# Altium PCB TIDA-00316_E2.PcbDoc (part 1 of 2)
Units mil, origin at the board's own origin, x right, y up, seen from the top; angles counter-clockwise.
Board outline 3345 x 4425 mil, 4 copper layers (Top Layer, L1_GND, L2_POWER, Bottom Layer), stack 90 mil thick; 218 components, 101 nets, 687 pads, 221 vias.
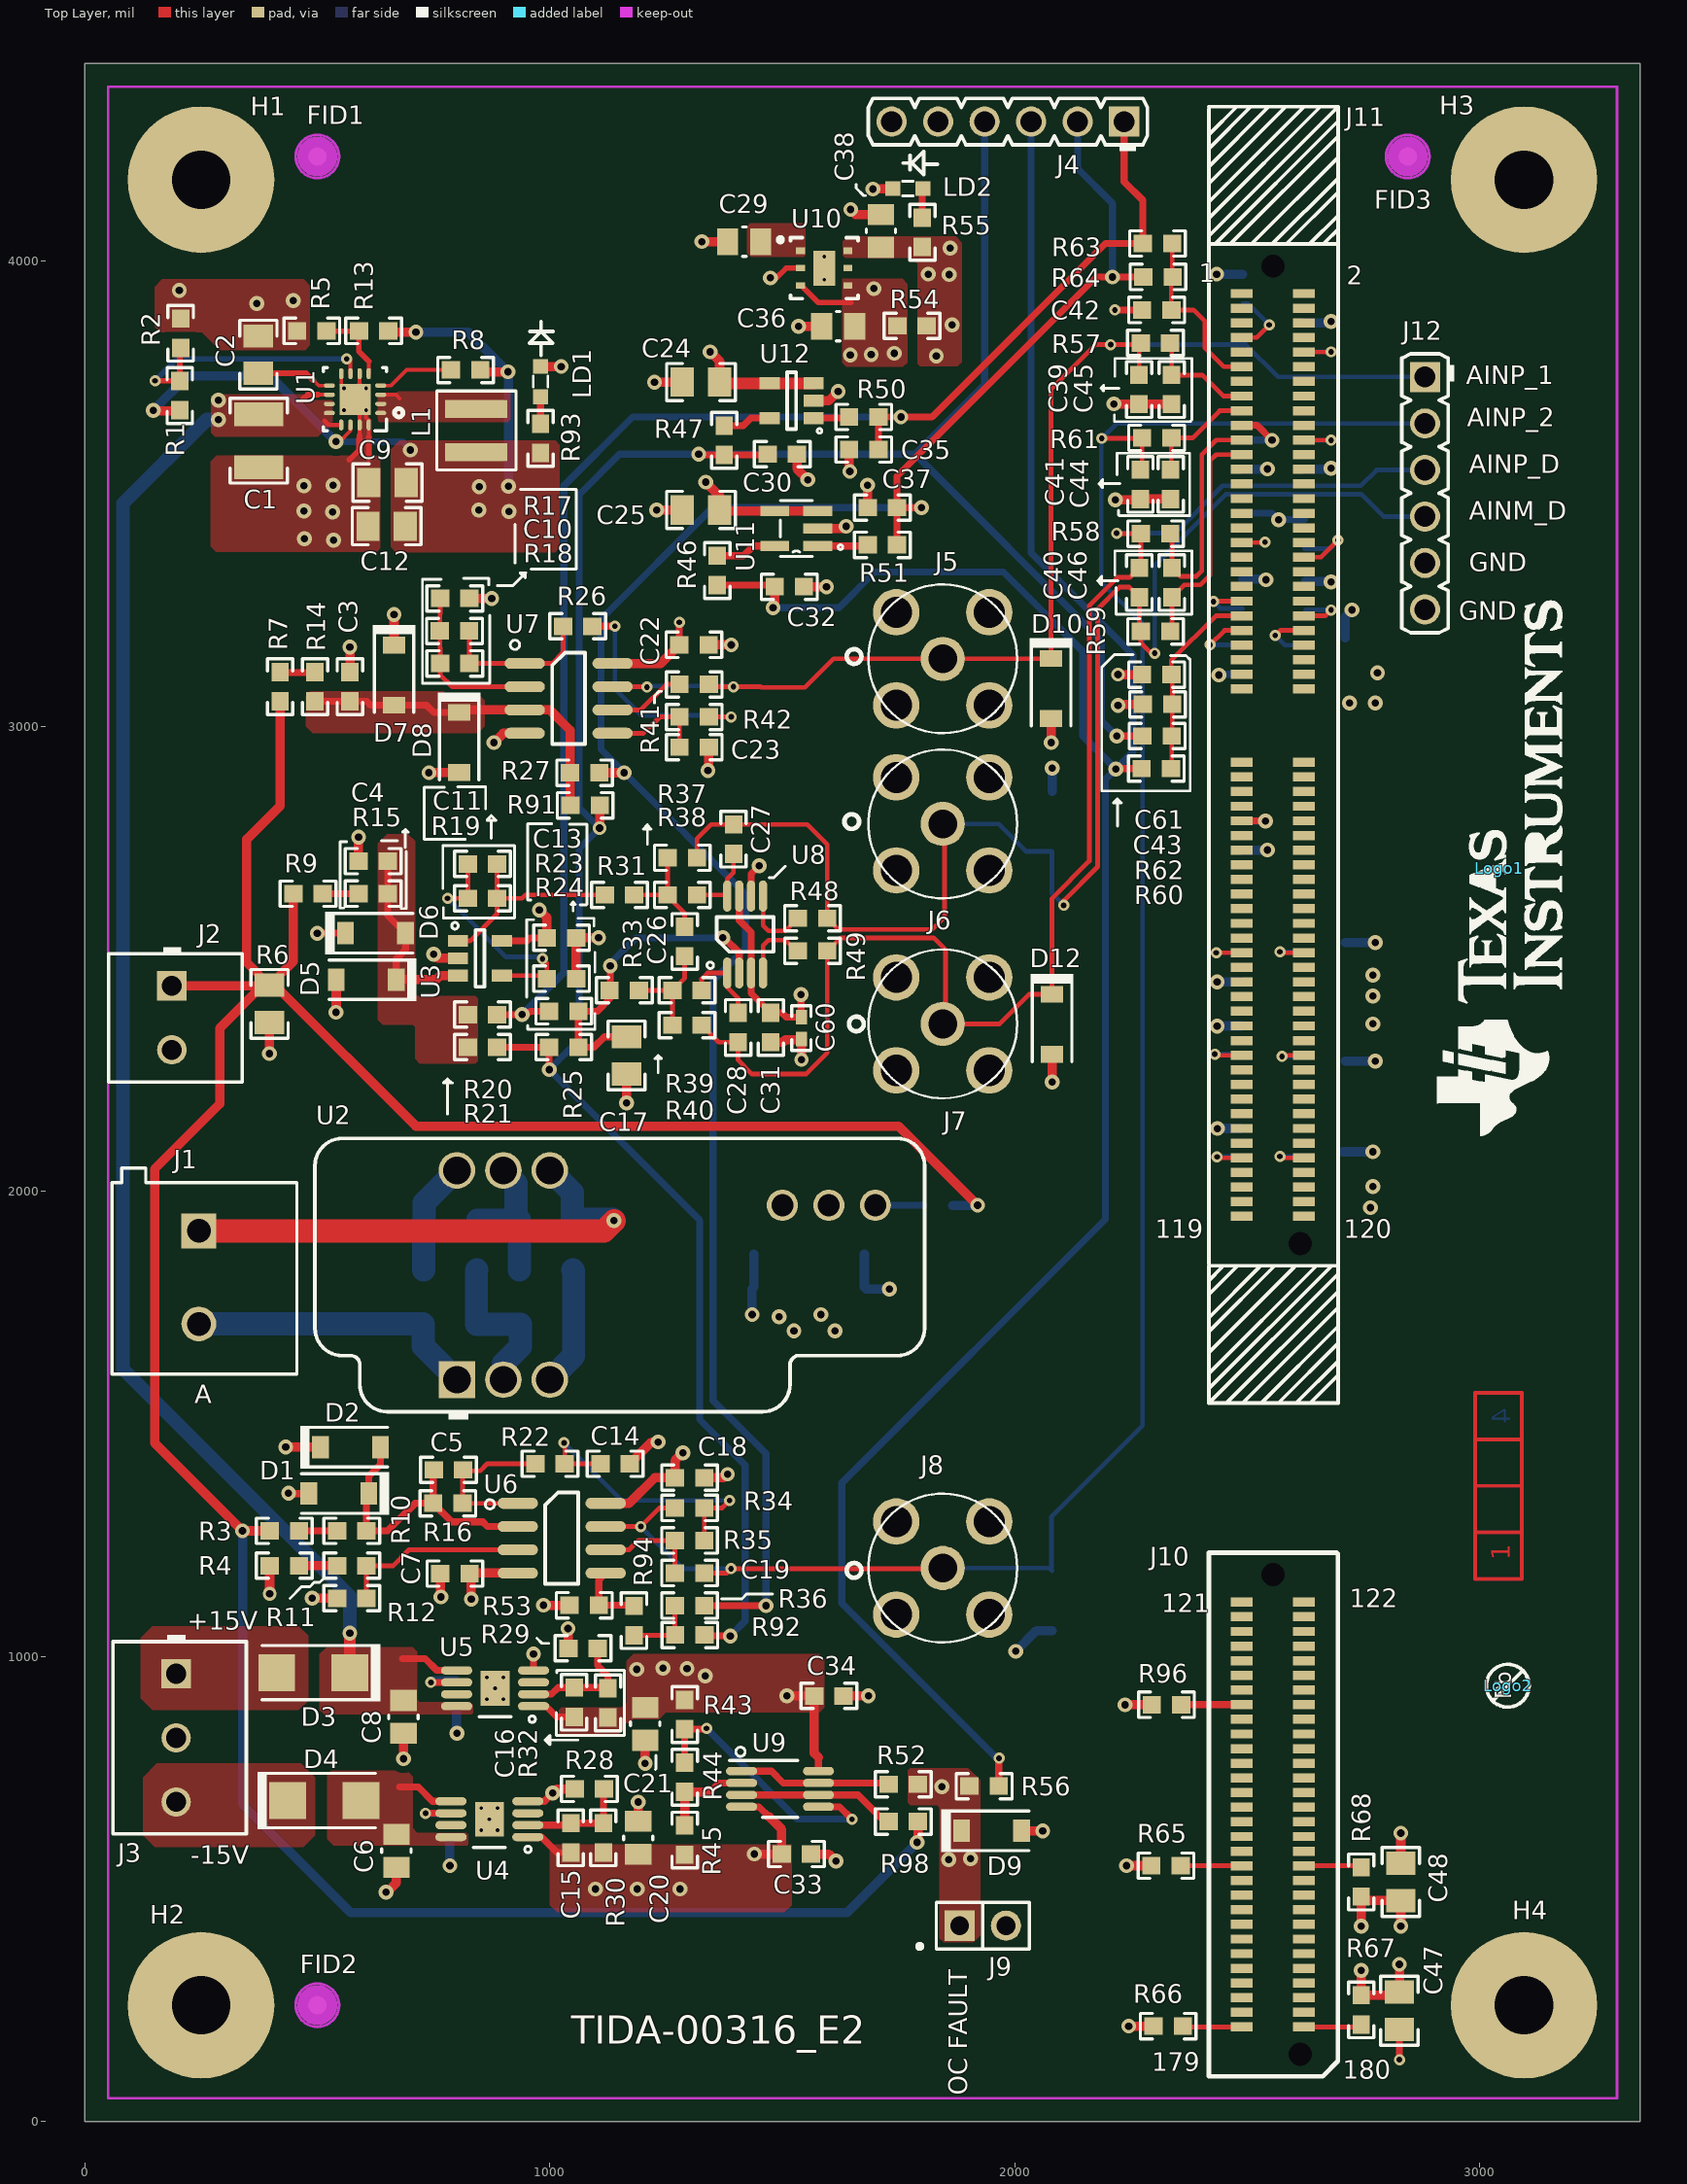
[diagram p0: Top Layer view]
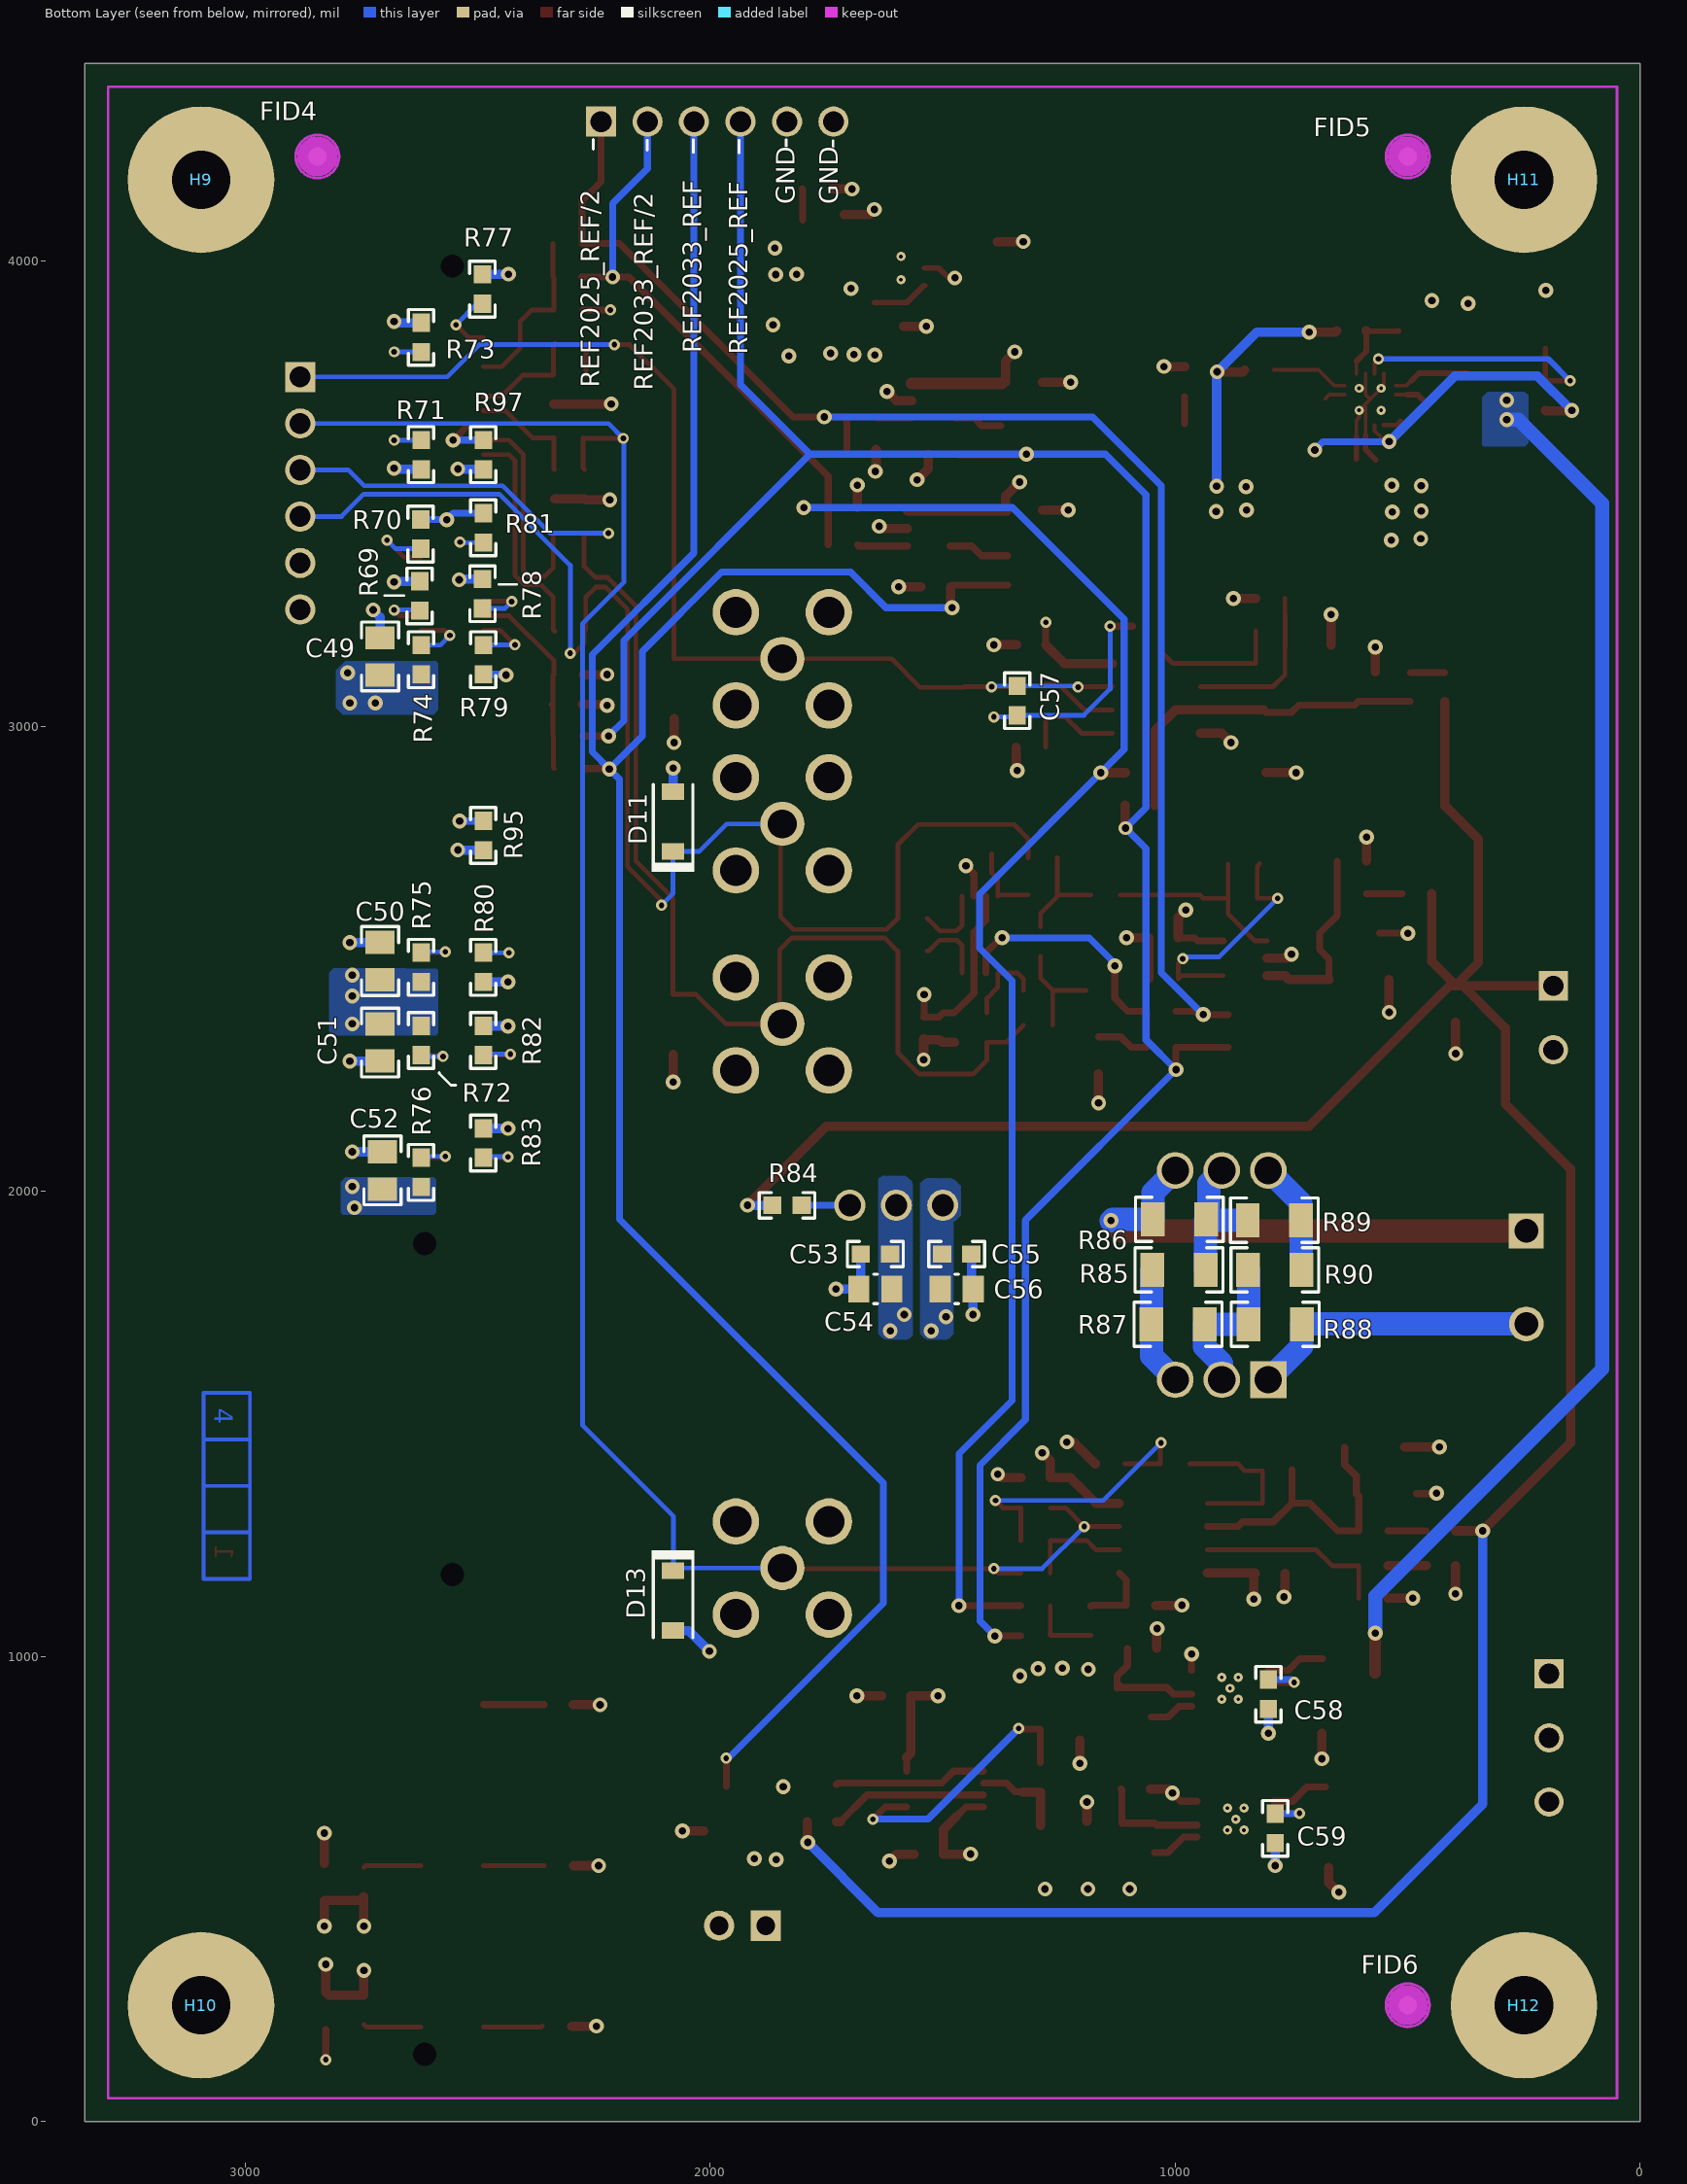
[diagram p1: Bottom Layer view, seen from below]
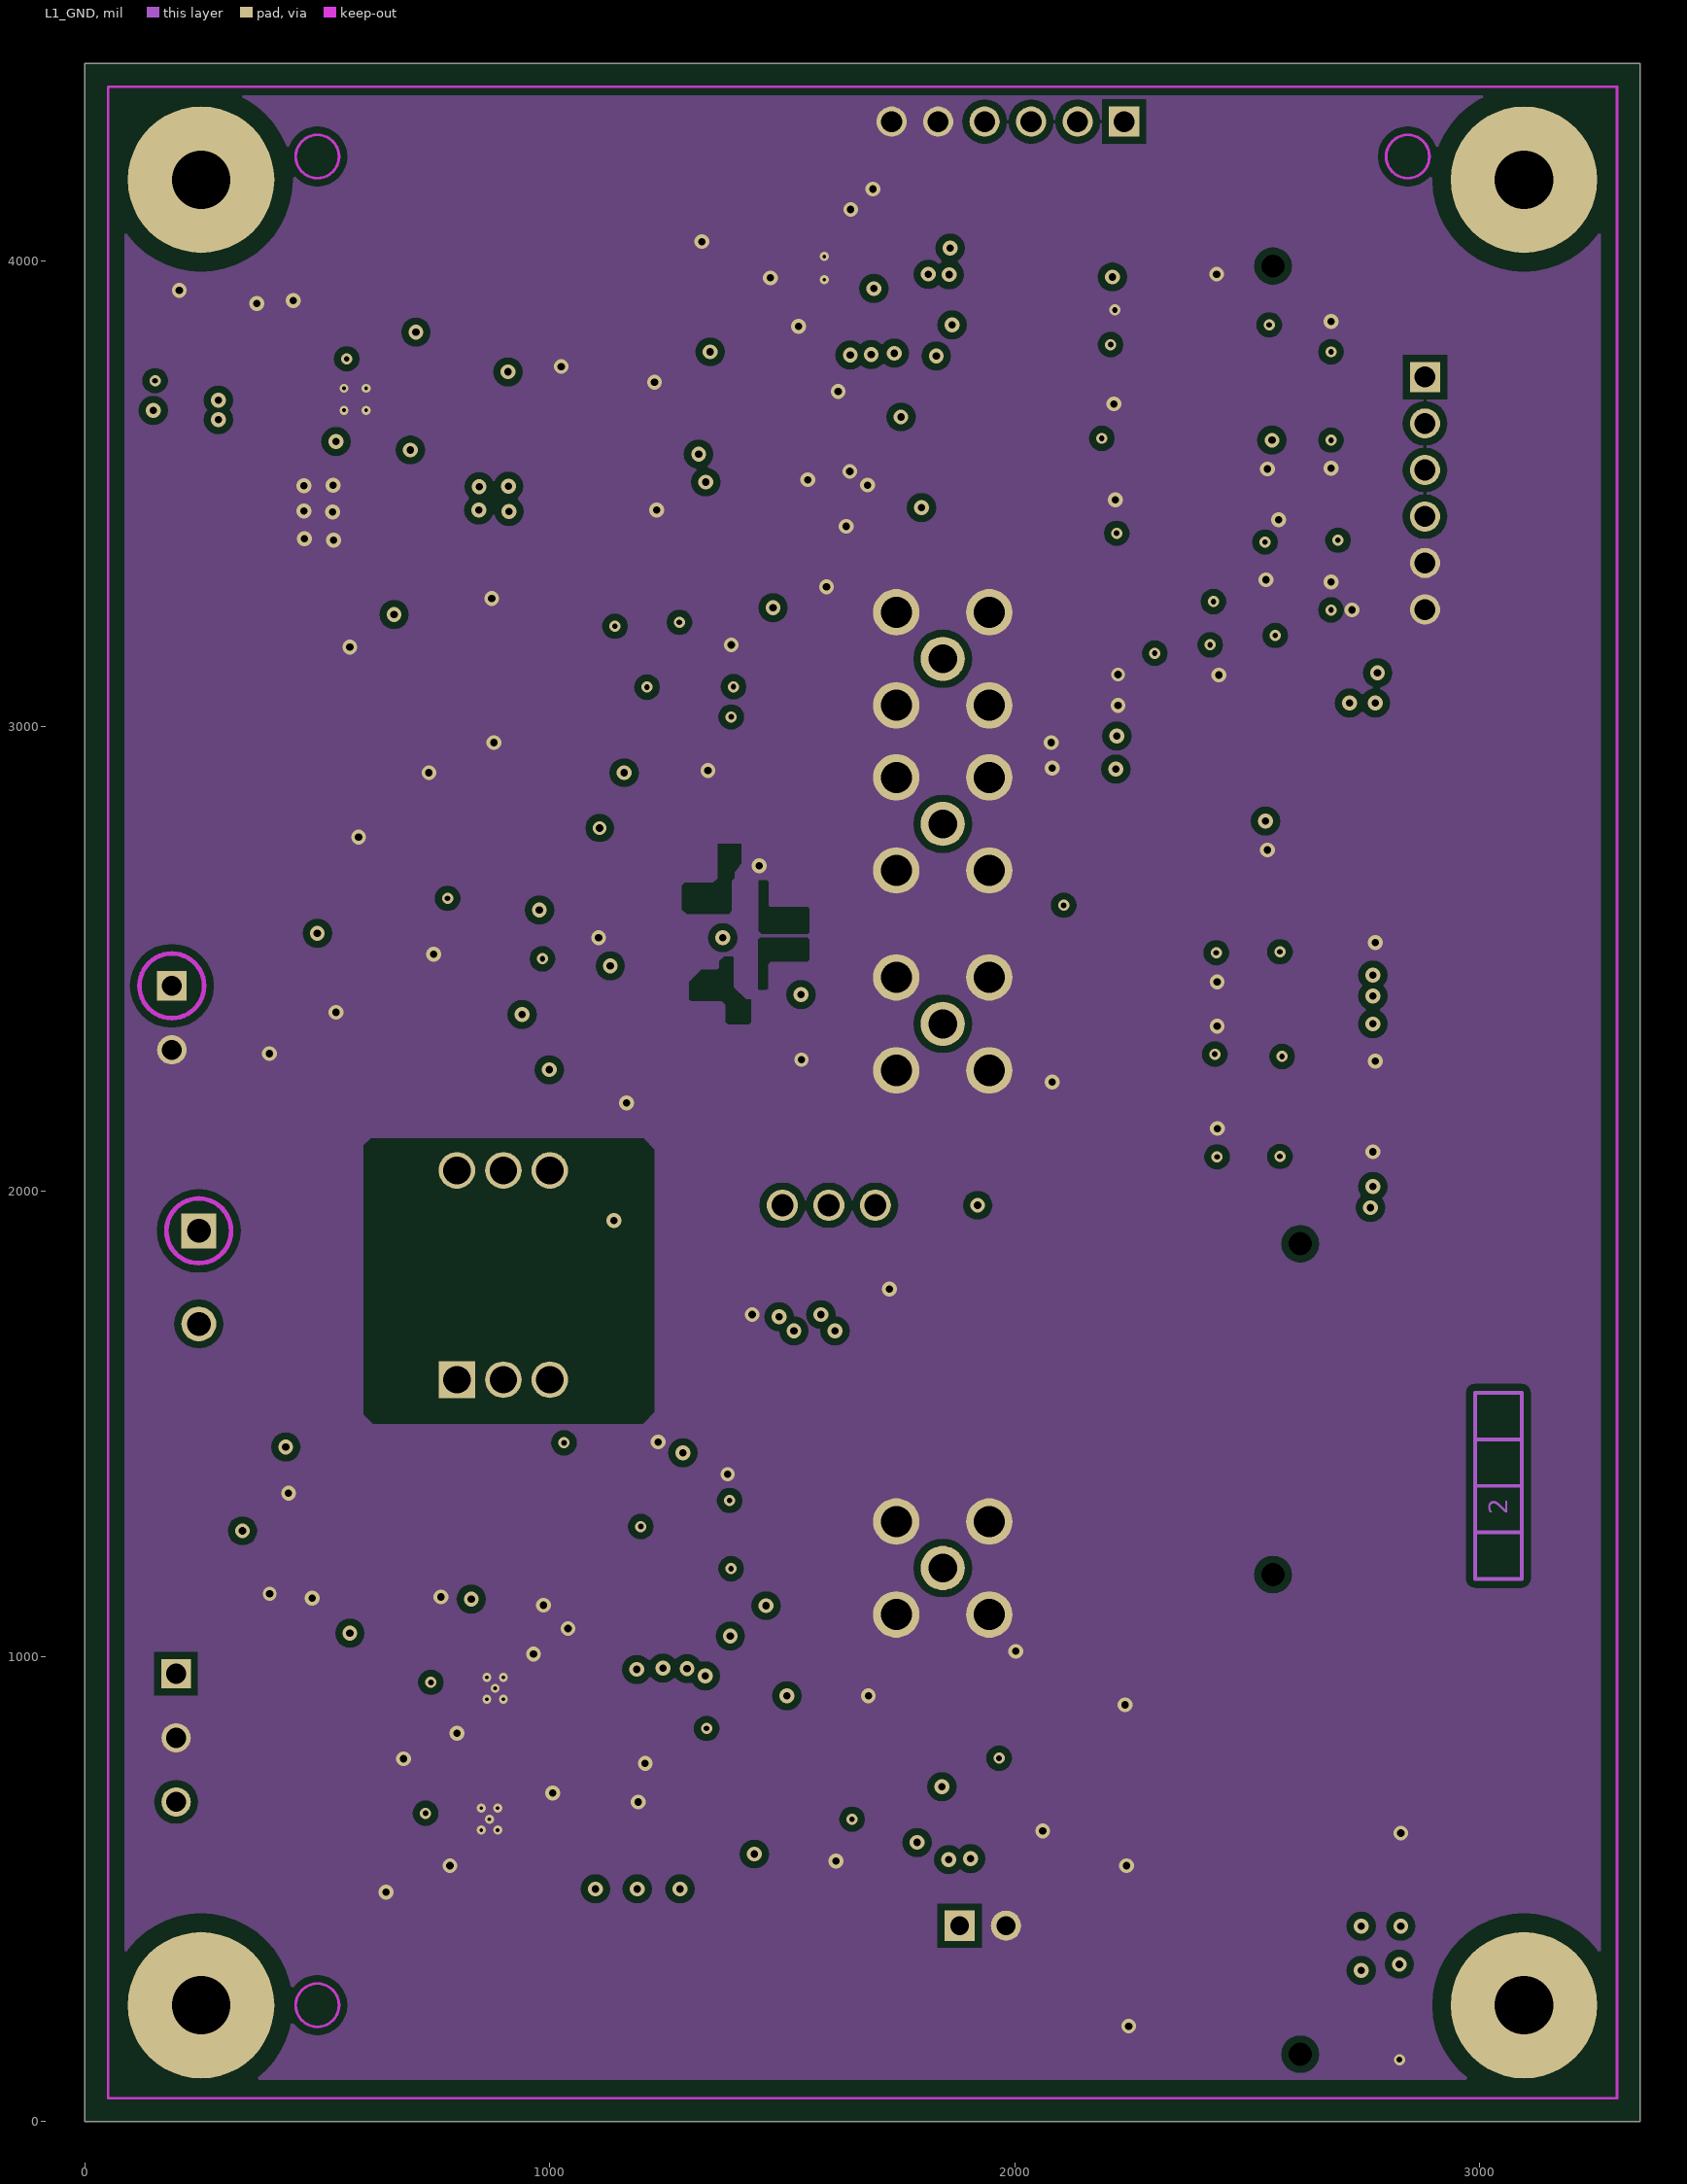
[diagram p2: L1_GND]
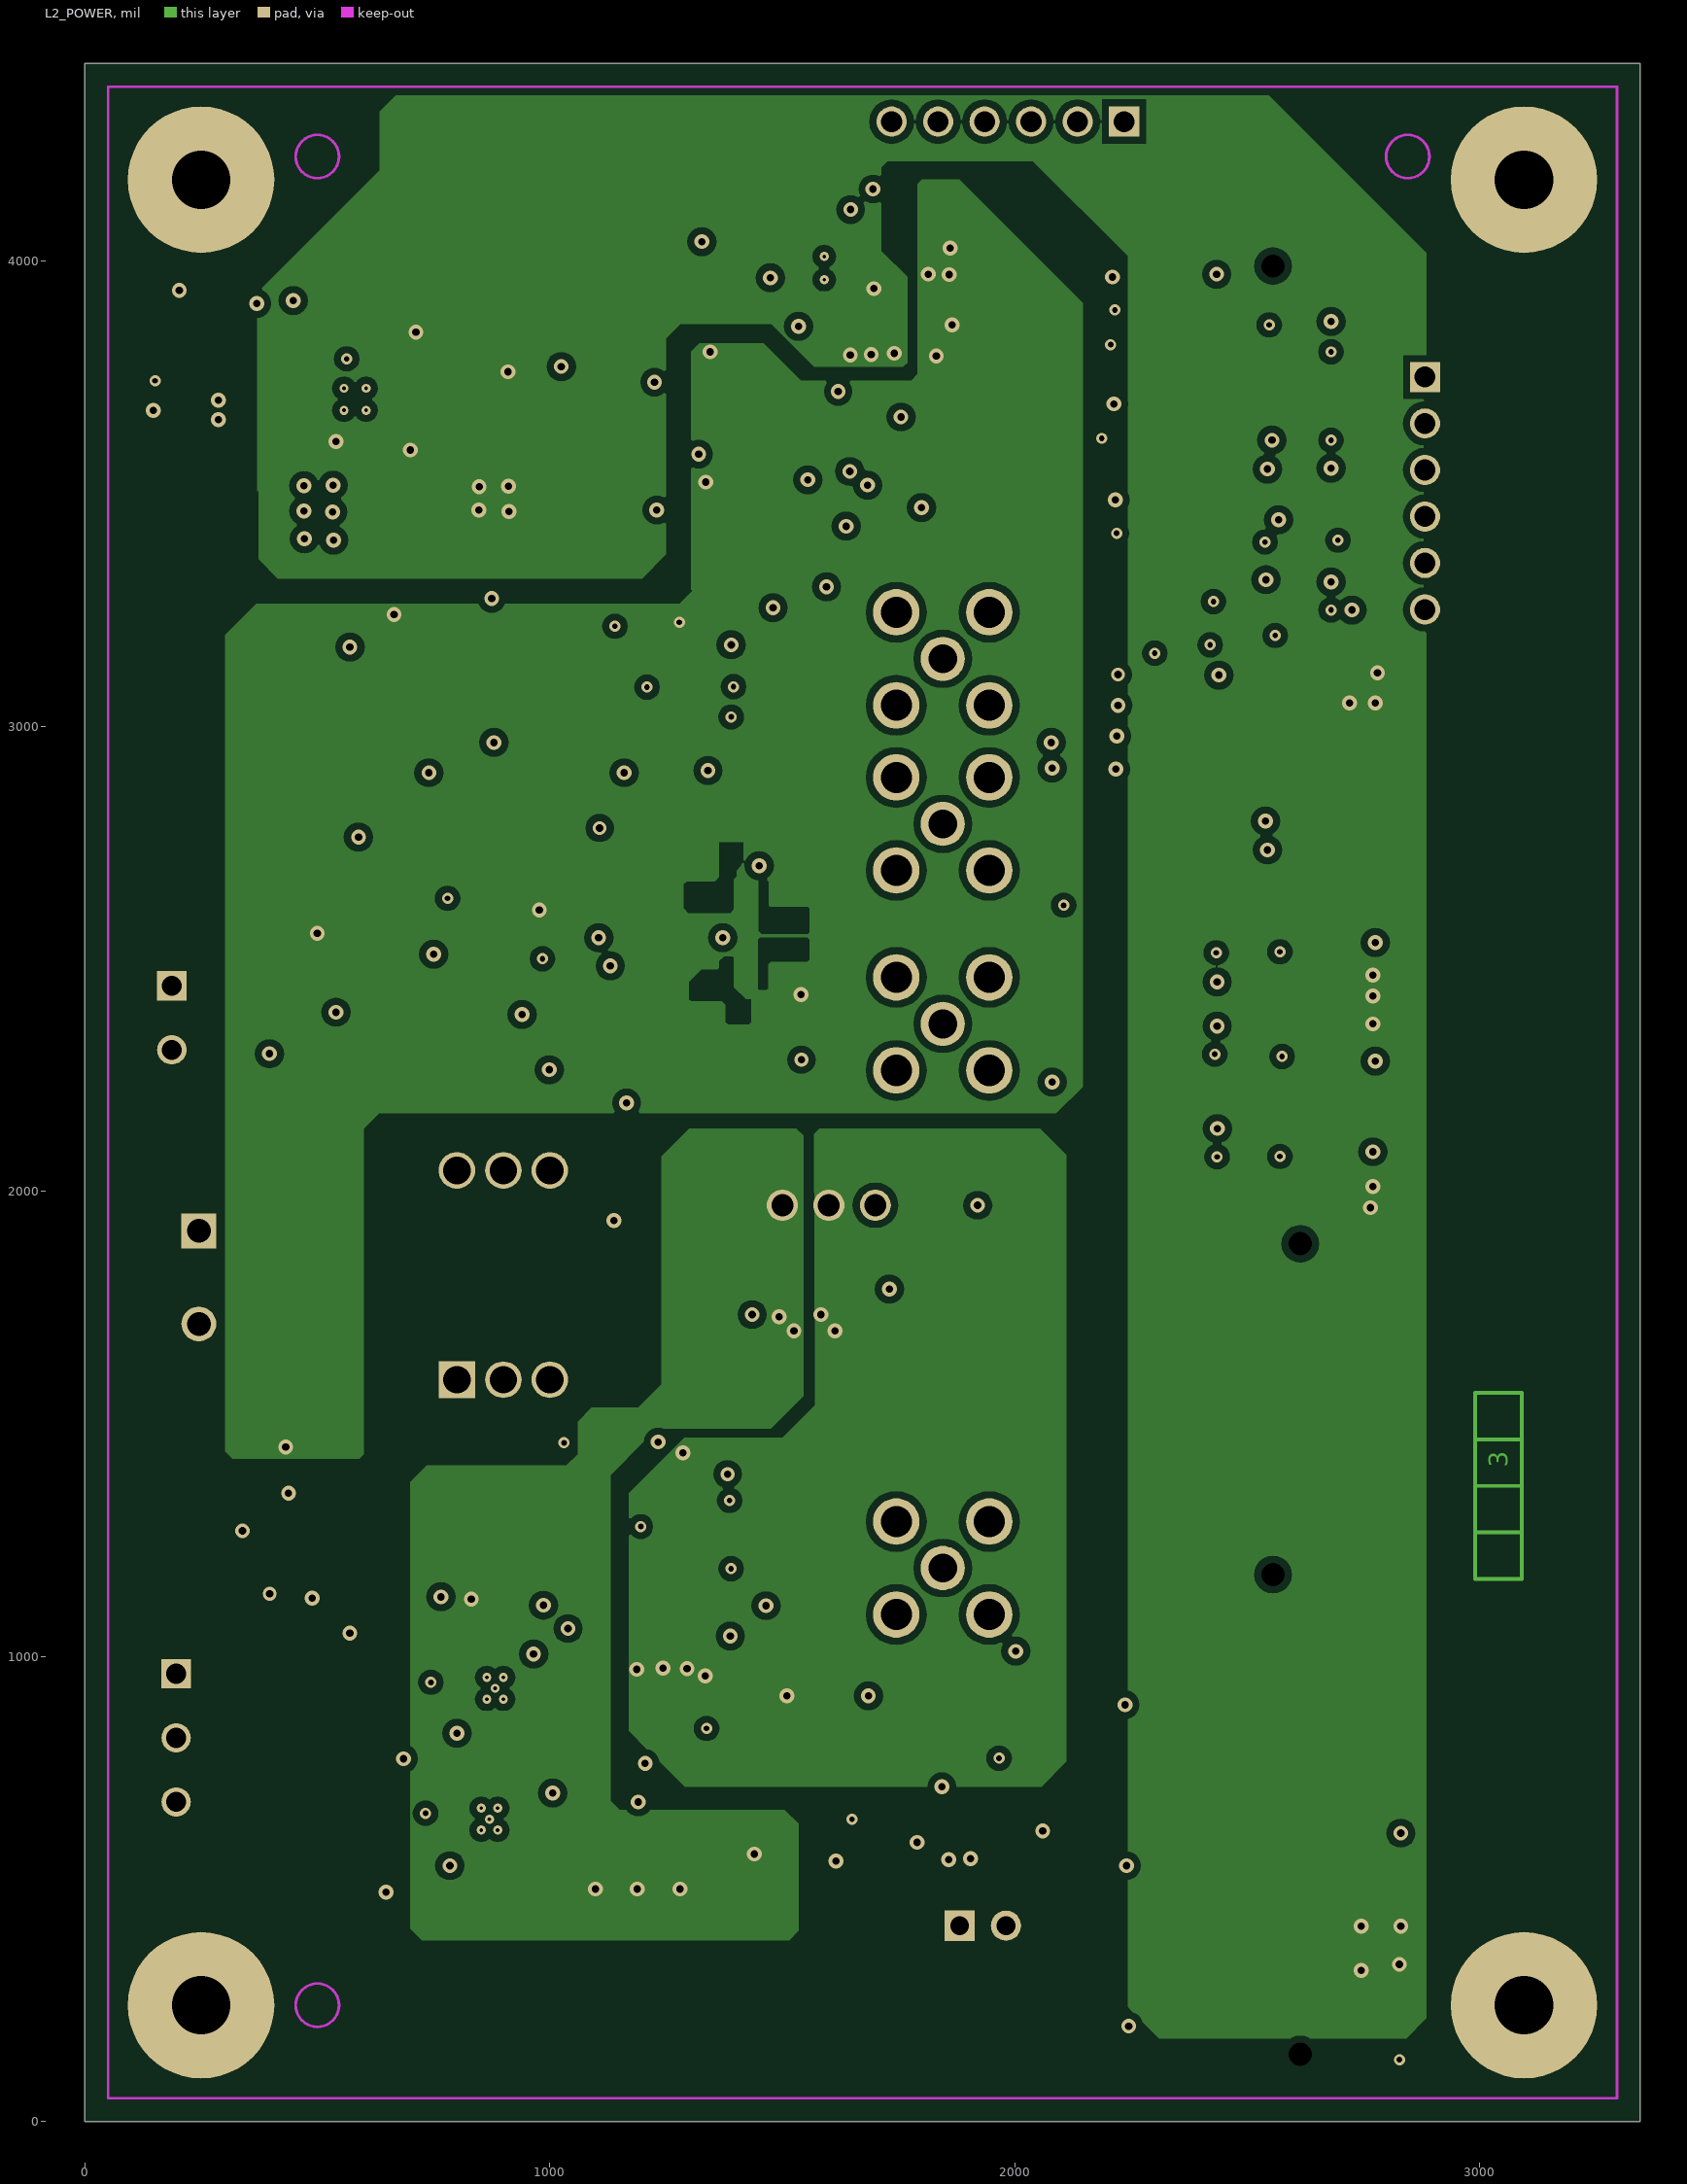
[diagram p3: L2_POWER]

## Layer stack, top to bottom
Top Layer: signal copper 1.4
Dielectric: core 59.2, FR-4, Dk 4.8
L1_GND: signal copper 1.4
Dielectric: prepreg 12.6, FR-4, Dk 4.8
L2_POWER: signal copper 1.4
Dielectric: core 12.6, FR-4, Dk 4.8
Bottom Layer: signal copper 1.4

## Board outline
0,0 3345,0 3345,4425 0,4425

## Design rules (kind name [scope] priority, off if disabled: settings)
AcuteAngle [All] p1: minimum=4.50000000000000E+0001 checktracksonly=FALSE
AssemblyTestPointUsage [All] p1: valid=2
Clearance Clearance_Boardedge_poly [OnCopper and InPolygon vs IsKeepOut] p1: gap=15
Clearance "Clearance_via_thr pin" [IsVia vs IsThruPin] p2: gap=8
Clearance Clearance_MTG_COPPER [InPadClass('MTG') vs InPolygon] p3: gap=40
Clearance "Clearance_pad _class" [InPadClass('U8')] p4: gap=7.8
Clearance "shape to all" [InPolygon] p5: gap=15
Clearance "Shape to Shape" [InPolygon vs InPolygon] p6: gap=25
Clearance "SMD to Via" [IsSMTPin vs IsVia] p7: gap=8
Clearance [All] p8: gap=8
DiffPairsRouting DiffPair_DiffPairsRouting [InDifferentialPair ('kan')] p1: maxlimit=10 minlimit=10 mostfreqgap=10 maxuncoupledlength=500
DiffPairsRouting DiffPair_DiffPairsRouting_1 [InDifferentialPair ('kan')] p2: maxlimit=10 minlimit=10 mostfreqgap=10 maxuncoupledlength=500
DiffPairsRouting [All] p3: maxlimit=100 minlimit=10 mostfreqgap=10 maxuncoupledlength=1000
FabricationTestPointUsage TestPointUsage [All] p1: valid=2 allowmultiple=FALSE
FabricationTestpoint Testpoint [All] p1: side=3 testpointundercomponent=TRUE minsize=40 maxsize=100 preferedsize=60 minholesize=0 maxholesize=40 preferedholesize=32 testpointgrid=1 allowsidetop=TRUE allowsidebottom=TRUE usegrid=TRUE gridtolerance=0.01
FanoutControl Fanout_LCC [IsLCC] p1: bgadir=Out bgaviamode=Centered fanoutstyle=Auto fanoutdirection=Alternating viagrid=1 // Fanout_LCC (Default Rule)
FanoutControl Fanout_BGA [IsBGA] p2: bgadir=Out bgaviamode=Centered fanoutstyle=Auto fanoutdirection=Alternating viagrid=1 // Fanout_BGA (Default Rule)
FanoutControl Fanout_Default [All] p4: bgadir=Out bgaviamode=Centered fanoutstyle=Auto fanoutdirection=Alternating viagrid=1 // Fanout_Default (Default Rule)
FanoutControl Fanout_Small [(CompPinCount < 5)] p5: bgadir=Out bgaviamode=Centered fanoutstyle=Auto fanoutdirection=OutThenIn viagrid=1 // Fanout_Small (Default Rule)
HoleSize [All] p1: absolutevalues=TRUE maxlimit=251 minlimit=7 maxpercent=80.000 minpercent=20.000
MatchedLengths DiffPair_MatchedLengths [InDifferentialPair ('kan')] p1: tolerance=1000 checknetsindiffpair=TRUE checkdiffpairvsdiffpair=TRUE checkothers=TRUE
MatchedLengths DiffPair_MatchedLengths_1 [InDifferentialPair ('kan')] p2: tolerance=1000 checknetsindiffpair=TRUE checkdiffpairvsdiffpair=TRUE checkothers=TRUE
MinimumAnnularRing [All] p1: minimumring=5
MinimumAnnularRing MinimumAnnularRing_ThermalPadVias [IsVia and InAnyComponent] p2: minimumring=5.91
MinimumSolderMaskSliver MinimumSolderMaskSliver_Logo [InComponentClass('Logo') vs InComponentClass('Logo')] p1: minsoldermaskwidth=0.7
MinimumSolderMaskSliver [All] p2: minsoldermaskwidth=3.94
PlaneClearance [All] p1: clearance=15
PlaneConnect [All] p1: planeconnectstyle=Direct reliefexpansion=10 reliefentries=4 reliefconductorwidth=10 reliefairgap=10
PolygonConnect [All] p1: connectstyle=Direct reliefconductorwidth=10 reliefentries=4 polygonreliefangle="90 Angle" airgapwidth=10
RoutingVias RoutingVias_power [InNetClass('POWER')] p1: holewidth=16 width=32 viastyle="Through Hole" minholewidth=7.87 minwidth=19.68 maxholewidth=16 maxwidth=32
RoutingVias ThermalPadVias [IsVia and InAnyComponent] p2: holewidth=8 width=20 viastyle="Through Hole" minholewidth=7.87 minwidth=19 maxholewidth=12 maxwidth=24
RoutingVias [All] p3: holewidth=12 width=24 viastyle="Through Hole" minholewidth=12 minwidth=24 maxholewidth=16 maxwidth=32
SMDToCorner [All] p1: distance=30000
SilkToSilkClearance [All] p1: silktosilkclearance=5
SilkscreenOverComponentPads [IsPad] p1: minsilkscreentomaskgap=5
SolderMaskExpansion [All] p1: expansion=3
Width Width_power [InNetClass('POWER')] p1: maxlimit=100 minlimit=8 preferedwidth=20
Width [All] p2: maxlimit=100 minlimit=8 preferedwidth=10 checkconnectedcopper=TRUE
14 further rules are at their usual default settings.

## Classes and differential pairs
pad class MTG: H1-1 H2-1 H3-1 H4-1
component class SH05_180_pin_connector_interface: C39 C40 C41 C42 C43 C44 C45 C46 C47 C48 C49 C50 C51 C52 C61 D10 D11 D12 D13 J10 J11 R57 R58 R59 R60 R61 R62 R63 R64 R65 R66 R67 R68 R69 R70 R71 R72 R73 R74 R75 R76 R77 R78 R79 R80 R81 R82 R83 R95 R96 R97
component class SH04_Fully_differential_ended_SC_to_ADC: C4 C11 C13 C17 C26 C27 C28 C31 C33 C34 C60 D5 D6 D9 J4 J6 J7 J9 J12 R9 R15 R19 R20 R21 R23 R24 R25 R31 R33 R37 R38 R39 R40 R43 R44 R45 R48 R49 R52 R56 R98 U3 U8 U9
component class SH03_Single_ended_SC_to_ADC: C3 C5 C7 C10 C14 C18 C19 C22 C23 C53 C54 C55 C56 C57 D1 D2 D7 D8 J1 J2 J5 J8 R3 R4 R6 R7 R10 R11 R12 R14 R16 R17 R18 R22 R26 R27 R34 R35 R36 R41 R42 R53 R84 R85 R86 R87 R88 R89 R90 R91 R92 R94 U2 U6 U7
component class SH02_Power_supply: C1 C2 C6 C8 C9 C12 C15 C16 C20 C21 C24 C25 C29 C30 C32 C35 C36 C37 C38 C58 C59 D3 D4 J3 L1 LD1 LD2 R1 R2 R5 R8 R13 R28 R29 R30 R32 R46 R47 R50 R51 R54 R55 R93 U1 U4 U5 U10 U11 U12
component class "Mounting Holes": H1 H2 H3 H4
component class Header: J4 J9 J12
component class AssemblyNote: ZZ1 ZZ2 ZZ3
component class Logo: Logo1
component class SH06_Hardware: FID1 FID2 FID3 FID4 FID5 FID6 H1 H2 H3 H4 H9 H10 H11 H12 Logo1 Logo2 ZZ1 ZZ2 ZZ3
component class FiducialMark: FID1 FID2 FID3 FID4 FID5 FID6
pad class U8: U4-1 U4-2 U4-3 U4-4 U4-5 U4-6 U4-7 U4-8 U4-9 U5-1 U5-2 U5-3 U5-4 U5-5 U5-6 U5-7 U5-8 U5-9 U8-1 U8-2 U8-3 U8-4 U8-5 U8-6 U8-7 U8-8 U9-1 U9-2 U9-3 U9-4 U9-5 U9-6 U9-7 U9-8

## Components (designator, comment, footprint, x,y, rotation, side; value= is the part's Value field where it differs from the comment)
C1 "C3216X7R1V106M160AC" 1210 374,3614 r270 top (schematic designator C6)
C2 "C0805C332K5RACTU" 0805_HV 373,3799 r90 top (schematic designator C7)
C3 "C1608C0G2A101J" 0603 570,3085 r90 top (schematic designator C31)
C4 "C1608C0G2A101J" 0603 620,2710 r180 top (schematic designator C48)
C5 "C1608C0G2A101J" 0603 782,1401 r180 top (schematic designator C32)
C6 "GRM21BR61E106KA73L" 0805_140 670,582 r270 top (schematic designator C16)
C7 "GRM188R71H104KA93D" 0603 796,1178 r180 top (schematic designator C36)
C8 "GRM21BR61E106KA73L" 0805_140 685,870 r270 top (schematic designator C12)
C9 "C2012X5R1C226K125AC" 0805_HV 651,3524 r180 top (schematic designator C53)
C10 "C1608C0G2A101J" 0603 795,3205 r180 top (schematic designator C24)
C11 "C1608C0G2A101J" 0603 855,2704 r180 top (schematic designator C44)
C12 "C2012X5R1C226K125AC" 0805_HV 649,3430 r180 top (schematic designator C57)
C13 "GRM188R71H104KA93D" 0603 1025,2545 r0 top (schematic designator C46)
C14 "C1608C0G1H272J" 0603 1140.57,1414.22 r0 top (schematic designator C35)
C15 "C1608C0G1E103J" 0603 1045,610 r90 top (schematic designator C17)
C16 "C1608C0G1E103J" 0603 1052.28,901.38 r90 top (schematic designator C13)
C17 "C0805C105K8RACTU" 0805_HV 1164.98,2292.2 r270 top (schematic designator C50)
C18 "GRM188R71H104KA93D" 0603 1300.57,1384.22 r0 top (schematic designator C34)
C19 "06035A471JAT2A" 0603 1300.57,1179.22 r180 top (schematic designator C33)
C20 "GRM21BR61E106KA73L" 0805_140 1190,610 r90 top (schematic designator C18)
C21 "GRM21BR61E106KA73L" 0805_140 1205,855 r270 top (schematic designator C14)
C22 "GRM188R71H104KA93D" 0603 1310,3175 r0 top (schematic designator C29)
C23 "C1608C0G2A101J" 0603 1310.43,2955 r0 top (schematic designator C30)
C24 "C0805C105K8RACTU" 0805_HV 1325,3740 r180 top (schematic designator C9)
C25 "C0805C105K8RACTU" 0805_HV 1325,3465 r180 top (schematic designator C19)
C26 "GRM1885C2A201JA01D" 0603 1289.98,2537.2 r270 top (schematic designator C47)
C27 "C1608C0G1H821J" 0603 1394.98,2757.2 r270 top (schematic designator C43)
C28 "C1608C0G1H821J" 0603 1404.98,2352.2 r90 top (schematic designator C49)
C29 "GRM21BR61E106KA73L" 0805_140 1418,4042 r180 top (schematic designator C3)
C30 "GRM188R71H104KA93D" 0603 1500,3585 r0 top (schematic designator C10)
C31 "GRM188R71H104KA93D" 0603 1474.98,2352.2 r270 top (schematic designator C45)
C32 "GRM188R71H104KA93D" 0603 1515,3300 r0 top (schematic designator C21)
C33 "GRM188R71H104KA93D" 0603 1530,575 r0 top (schematic designator C37)
C34 "GRM188R71H104KA93D" 0603 1600,915 r0 top (schematic designator C39)
C35 "GRM188R71H104KA93D" 0603 1675,3595 r180 top (schematic designator C11)
C36 "GRM21BR61E106KA73L" 0805_140 1620,3860 r180 top (schematic designator C1)
C37 "GRM188R71H104KA93D" 0603 1715,3470 r180 top (schematic designator C22)
C38 "GRM21BR61E106KA73L" 0805_140 1712,4065 r90 top (schematic designator C2)
C39 "C1608C0G1H331F080AA" 0603 2267.2,3724 r270 top (schematic designator C38)
C40 "C1608C0G1H331F080AA" 0603 2267.73,3309 r270 top (schematic designator C51)
C41 "C1608C0G1H331F080AA" 0603 2270,3520 r270 top
C42 "0603ZD475KAT2A" 0603 2305,3895 r180 top (schematic designator C58)
C43 "0603ZD475KAT2A" 0603 2307,3047 r180 top (schematic designator C59)
C44 "C1608C0G1H331F080AA" 0603 2335,3520 r270 top (schematic designator C42)
C45 "C1608C0G1H331F080AA" 0603 2337.2,3724 r270 top (schematic designator C40)
C46 "C1608C0G1H331F080AA" 0603 2337.73,3309 r270 top (schematic designator C52)
C47 "C0805C105K8RACTU" 0805_HV 2827,238 r270 top (schematic designator C5)
C48 "C0805C105K8RACTU" 0805_HV 2830,515 r90 top (schematic designator C56)
C49 "C0805C105K8RACTU" 0805_HV 2710,3150 r90 bottom (schematic designator C55)
C50 "C0805C105K8RACTU" 0805_HV 2710,2495 r90 bottom (schematic designator C4)
C51 "C0805C105K8RACTU" 0805_HV 2710,2320 r270 bottom (schematic designator C8)
C52 "C0805C105K8RACTU" 0805_HV 2705,2045 r90 bottom (schematic designator C54)
C53 "GRM188R71H104KA93D" 0603 1645,1865 r0 bottom (schematic designator C25)
C54 "GRM21BR61E106KA73L" 0805_140 1645,1790 r0 bottom (schematic designator C26)
C55 "GRM188R71H104KA93D" 0603 1470,1865 r180 bottom (schematic designator C28)
C56 "GRM21BR61E106KA73L" 0805_140 1470,1790 r180 bottom (schematic designator C27)
C57 "GRM1885C2A201JA01D" 0603 1340,3055 r270 bottom (schematic designator C23)
C58 "C1608C0G1E103J" 0603 799.61,918.58 r270 bottom (schematic designator C15)
C59 "C1608C0G1E103J" 0603 785,630 r270 bottom (schematic designator C20)
C60 "C0402C103J5RACTU" 0402 1541,2351 r270 top
C61 "C1608C0G1H331F080AA" 0603 2305,3111 r180 top
D1 "SD101CW-7-F" SOD-123#1 546,1350 r180 top (schematic designator D7)
D2 "SD101CW-7-F" SOD-123#1 571,1450 r0 top (schematic designator D8)
D3 "MBRA160T3G" SMA 491.18,965 r180 top (schematic designator D2)
D4 "MBRA160T3G" SMA 515,690 r0 top (schematic designator D3)
D5 "SD101CW-7-F" SOD-123#1 605,2455 r180 top (schematic designator D11)
D6 "SD101CW-7-F" SOD-123#2 625,2555 r0 top (schematic designator D12)
D7 "SD101CW-7-F" SOD-123#1 665,3110 r270 top (schematic designator D6)
D8 "SD101CW-7-F" SOD-123#1 805,2965 r270 top (schematic designator D5)
D9 "SD101CW-7-F" SOD-123#2 1950,625 r0 top
D10 "MMSZ5227B-7-F" SOD-123#1 2078,3081 r270 top (schematic designator D13)
D11 "MMSZ5227B-7-F" SOD-123#1 2080,2795 r90 bottom (schematic designator D16)
D12 "MMSZ5227B-7-F" SOD-123#1 2080,2359 r270 top (schematic designator D15)
D13 "MMSZ5227B-7-F" SOD-123#1 2080,1120 r270 bottom (schematic designator D14)
FID1 "Fiducial" Fiducial10-20 500,4225 r90 top (schematic designator FID2)
FID2 "Fiducial" Fiducial10-20 500,250 r90 top (schematic designator FID1)
FID3 "Fiducial" Fiducial10-20 2845,4225 r90 top
FID4 "Fiducial" Fiducial10-20 2845,4225 r90 bottom (schematic designator FID6)
FID5 "Fiducial" Fiducial10-20 500,4225 r90 bottom
FID6 "Fiducial" Fiducial10-20 500,250 r90 bottom (schematic designator FID4)
H1 "NY PMS 440 0025 PH" "NY PMS 440 0025 PH" 250,4175 r0 top (schematic designator H2)
H2 "NY PMS 440 0025 PH" "NY PMS 440 0025 PH" 250,250 r0 top (schematic designator H1)
H3 "NY PMS 440 0025 PH" "NY PMS 440 0025 PH" 3095,4175 r0 top
H4 "NY PMS 440 0025 PH" "NY PMS 440 0025 PH" 3095,250 r0 top
H9 "1902C" Keystone_1902C 3095,4175 r180 bottom (schematic designator H7)
H10 "1902C" Keystone_1902C 3095,250 r180 bottom (schematic designator H8)
H11 "1902C" Keystone_1902C 250,4175 r180 bottom (schematic designator H6)
H12 "1902C" Keystone_1902C 250,250 r180 bottom (schematic designator H5)
J1 "1715721" PhoenixContact_1715721 245,1815 r270 top (schematic designator J2)
J2 "39357-0002" Molex_39357-0002 187,2373 r270 top (schematic designator J5)
J3 "39357-0003" Molex_39357-0003 196.18,825 r270 top (schematic designator J1)
J4 "61300611121" WURTH_61300611121 1985,4300 r180 top (schematic designator J9)
J5 "142-0701-201" JOHNSON_142-0701-20X 1845,3145 r0 top (schematic designator J4)
J6 "142-0701-201" JOHNSON_142-0701-20X 1845,2790 r0 top (schematic designator J7)
J7 "142-0701-201" JOHNSON_142-0701-20X 1845,2360 r0 top (schematic designator J8)
J8 "142-0701-201" JOHNSON_142-0701-20X 1845,1190 r0 top (schematic designator J6)
J9 "90120-0122" CONN_90120-0122 1931,421 r0 top (schematic designator J10)
J10 "SPD08-060-RB-TR" HSEC8-130-01-L-DV-A 2555,660 r90 top locked (schematic designator J12)
J11 "SPD08-120-L-RB" HSEC8-160-01-L-DV-A-L 2555,2938.29 r90 top locked
J12 "61300611121" WURTH_61300611121 2882,3501 r270 top (schematic designator J3)
L1 "XFL4020-222MEB" XFL4020 842,3636 r270 top
LD1 "LED_LG L29K-G2J1-24-Z" LED0603AA 980,3741 r270 top (schematic designator LD2)
LD2 "LED_LG L29K-G2J1-24-Z" LED0603AA 1770,4156 r0 top (schematic designator LD1)
Logo1 "Texas Instruments" TI_STACKED_OVERLAY_MEDIUM 3042,2695 r90 top
Logo2 "Pb-Free Symbol" Pb-Free_Overlay_Small 3060,937 r90 top
R1 "CRCW06030000Z0EA" 0603 204,3711 r270 top (schematic designator R52)
R2 "CRCW06030000Z0EA" 0603 206,3845 r270 top
R3 "CRCW06030000Z0EA" 0603 429,1270 r180 top (schematic designator R28)
R4 "CRCW06030000Z0EA" 0603 429,1195 r180 top (schematic designator R34)
R5 "CRCW0603154KFKEA" 0603 488,3850 r0 top (schematic designator R51)
R6 "CRCW080542R2FKEA" 0805_HV 397,2403 r90 top (schematic designator R23)
R7 "CRCW06030000Z0EA" 0603 420,3085 r270 top (schematic designator R21)
R8 "CRCW06031K00FKEA" 0603 819,3766 r0 top (schematic designator R48)
R9 "CRCW06030000Z0EA" 0603 480,2640 r180 top (schematic designator R65)
R10 "RC0603FR-072KL" 0603 574,1270 r0 top (schematic designator R29)
R11 "RC0603FR-072KL" 0603 574,1195 r180 top (schematic designator R35)
R12 "RC0603FR-072KL" 0603 574,1125 r180 top (schematic designator R36)
R13 "CRCW06031M00JNEA" 0603 621,3850 r0 top (schematic designator R50)
R14 "RC0603FR-072KL" 0603 495,3085 r270 top (schematic designator R22)
R15 "RC0603FR-072KL" 0603 620,2640 r0 top (schematic designator R66)
R16 "RC0603FR-072KL" 0603 780.57,1329.22 r180 top (schematic designator R26)
R17 "RC0603FR-072KL" 0603 795.43,3275 r180 top (schematic designator R15)
R18 "RC0603FR-072KL" 0603 795.43,3135 r180 top (schematic designator R12)
R19 "RC0603FR-072KL" 0603 855,2630 r180 top (schematic designator R59)
R20 "RC0603FR-072KL" 0603 855,2380 r180 top (schematic designator R71)
R21 "RC0603FR-072KL" 0603 855,2310 r180 top (schematic designator R17)
R22 "RT0603BRD07673RL" 0603 1000.57,1414.22 r0 top (schematic designator R32)
R23 "RC0603FR-072KL" 0603 1024.98,2457.2 r180 top (schematic designator R62)
R24 "CRCW06030000Z0EA" 0603 1029.98,2387.2 r180 top (schematic designator R67)
R25 "CRCW06030000Z0EA" 0603 1030,2310 r180 top (schematic designator R20)
R26 "CRCW06035K23FKEA" 0603 1060,3215 r0 top (schematic designator R18)
R27 "RC0603FR-072KL" 0603 1075,2900 r180 top (schematic designator R24)
R28 "CRCW06032K00FKEA" 0603 1085,715 r0 top (schematic designator R11)
R29 "CRCW06032K00FKEA" 0603 1071.28,1017.38 r0 top (schematic designator R7)
R30 "CRCW060318K2FKEA" 0603 1115,610 r270 top (schematic designator R8)
R31 "RG1608P-202-B-T5" 0603 1149.98,2637.2 r0 top (schematic designator R63)
R32 "CRCW060318K2FKEA" 0603 1125,900 r270 top (schematic designator R6)
R33 "RG1608P-202-B-T5" 0603 1159.98,2432.2 r0 top (schematic designator R68)
R34 "RT0603BRD07673RL" 0603 1300.57,1319.22 r180 top (schematic designator R27)
R35 "CRCW06031K15FKEA" 0603 1300.57,1249.22 r180 top (schematic designator R33)
R36 "CRCW06030000Z0EA" 0603 1300.57,1109.22 r0 top (schematic designator R38)
R37 "RG1608P-202-B-T5" 0603 1284.98,2717.2 r0 top (schematic designator R58)
R38 "CRCW06030000Z0EA" 0603 1284.98,2637.2 r180 top (schematic designator R64)
R39 "CRCW06030000Z0EA" 0603 1294.98,2432.2 r180 top (schematic designator R69)
R40 "RG1608P-202-B-T5" 0603 1294.98,2357.2 r0 top (schematic designator R77)
R41 "CRCW06030000Z0EA" 0603 1310.43,3090 r180 top (schematic designator R13)
R42 "CRCW06039K76FKEA" 0603 1310.43,3020 r180 top (schematic designator R19)
R43 "CRCW060343K2FKEA" 0603 1290,875 r90 top (schematic designator R45)
R44 "RC0603FR-0720KL" 0603 1290,740 r90 top (schematic designator R49)
R45 "CRCW060343K2FKEA" 0603 1290,605 r90 top (schematic designator R55)
R46 "CRCW06030000Z0EA" 0603 1360,3335 r90 top (schematic designator R9)
R47 "CRCW06030000Z0EA" 0603 1375,3615 r90 top (schematic designator R4)
R48 "CRCW060324R9FKEA" 0603 1564.98,2587.2 r180 top (schematic designator R46)
R49 "CRCW060324R9FKEA" 0603 1564.98,2517.2 r180 top (schematic designator R47)
R50 "CRCW06030000Z0EA" 0603 1675,3665 r180 top (schematic designator R5)
R51 "CRCW06030000Z0EA" 0603 1715,3390 r180 top (schematic designator R10)
R52 "CRCW060310K0FKEA" 0603 1760,725 r0 top (schematic designator R43)
R53 "RT0603DRE07511RL" 0603 1074,1110 r180 top
R54 "CRCW06030000Z0EA" 0603 1779,3861 r180 top (schematic designator R3)
R55 "RT0603DRE07511RL" 0603 1801,4062 r270 top
R56 "CRCW06032K49FKEA" 0603 1934,721 r0 top (schematic designator R41)
R57 "CRCW060322R0JNEA" 0603 2302.2,3824 r0 top (schematic designator R25)
R58 "CRCW060322R0JNEA" 0603 2302.73,3414 r0 top (schematic designator R37)
R59 "CRCW060322R0JNEA" 0603 2302.73,3204 r0 top (schematic designator R39)
R60 "CRCW06030000Z0EA" 0603 2304,2909 r0 top (schematic designator R44)
R61 "CRCW060322R0JNEA" 0603 2305,3620 r0 top (schematic designator R31)
R62 "CRCW06030000Z0EA" 0603 2306,2979 r0 top (schematic designator R113)
R63 "CRCW06030000Z0EA" 0603 2307,4038 r0 top (schematic designator R112)
R64 "CRCW06030000Z0EA" 0603 2308,3966 r0 top (schematic designator R42)
R65 "CRCW06030000Z0EA" 0603 2325,550 r0 top (schematic designator R110)
R66 "CRCW06030000Z0EA" 0603 2330,205 r0 top (schematic designator R120)
R67 "CRCW06030000Z0EA" 0603 2745,240 r90 top (schematic designator R121)
R68 "CRCW06030000Z0EA" 0603 2745,515 r270 top (schematic designator R111)
R69 "CRCW06030000Z0EA" 0603 2625,3280 r270 bottom (schematic designator R114)
R70 "CRCW06030000Z0EA" 0603 2623,3413 r270 bottom (schematic designator R107)
R71 "CRCW06030000Z0EA" 0603 2621.93,3583.96 r90 bottom (schematic designator R100)
R72 "CRCW06030000Z0EA" 0603 2621.93,2324.11 r90 bottom (schematic designator R109)
R73 "CRCW06030000Z0EA" 0603 2621.93,3835.93 r270 bottom (schematic designator R89)
R74 "CRCW06030000Z0EA" 0603 2621.93,3143.01 r270 bottom (schematic designator R119)
R75 "CRCW06030000Z0EA" 0603 2621.93,2481.6 r270 bottom (schematic designator R105)
R76 "CRCW06030000Z0EA" 0603 2621.93,2040.65 r270 bottom (schematic designator R118)
R77 "CRCW06030000Z0EA" 0603 2490,3940 r90 bottom (schematic designator R87)
R78 "CRCW06030000Z0EA" 0603 2490,3285 r270 bottom (schematic designator R115)
R79 "CRCW06030000Z0EA" 0603 2488.07,3143.01 r90 bottom (schematic designator R116)
R80 "CRCW06030000Z0EA" 0603 2488.07,2481.6 r90 bottom (schematic designator R104)
R81 "CRCW06030000Z0EA" 0603 2488.07,3426.48 r270 bottom (schematic designator R106)
R82 "CRCW06030000Z0EA" 0603 2488.07,2324.11 r270 bottom (schematic designator R108)
R83 "CRCW06030000Z0EA" 0603 2488.07,2103.64 r270 bottom (schematic designator R117)
R84 "CRCW06030000Z0EA" 0603 1835,1970 r0 bottom (schematic designator R14)
R85 "RC1206JR-070RL" 1206 992,1831 r180 bottom (schematic designator R53)
R86 "RC1206JR-070RL" 1206 991,1940 r180 bottom (schematic designator R70)
R87 "RC1206JR-070RL" 1206 994,1714 r0 bottom (schematic designator R61)
R88 "RC1206JR-070RL" 1206 785,1714 r0 bottom (schematic designator R56)
R89 "RC1206JR-070RL" 1206 787,1938 r180 bottom (schematic designator R57)
R90 "RC1206JR-070RL" 1206 786,1831 r180 bottom (schematic designator R54)
R91 "RC0603FR-072KL" 0603 1076,2830 r180 top
R92 "CRCW06030000Z0EA" 0603 1301,1046 r0 top
R93 "RT0603DRE07511RL" 0603 980,3619 r270 top
R94 "RT0603DRE07511RL" 0603 1181,1077 r90 top
R95 "CRCW06030000Z0EA" 0603 2488.07,2765.06 r90 bottom
R96 "CRCW06030000Z0EA" 0603 2326,896 r0 top
R97 "CRCW06030000Z0EA" 0603 2488.07,3583.96 r90 bottom
R98 "CRCW06030000Z0EA" 0603 1760,645 r180 top
U1 "TPS62150RGTT" RGT0016C 581,3703 r180 top (schematic designator U2)
U2 "LAH 25-NP" LAH25-NP 1250,1820 r90 top (schematic designator U7)
U3 "OPA322AIDBVR" DBV0005A_N 849.64,2501 r0 top (schematic designator U13)
U4 "TPS7A3001DGNR" DGN0008D_N 870,650 r180 top (schematic designator U5)
U5 "TPS7A4901DGNR" DGN0008D_N 882.28,931.38 r180 top (schematic designator U4)
U6 "OPA2192IDR" D0008A_N 1025.57,1254.22 r0 top (schematic designator U9)
U7 "OPA2322AIDR" D0008A_N 1040.43,3060 r0 top (schematic designator U8)
U8 "THS4531AIDGK" DGK0008A_N#1 1419.98,2552.2 r90 top (schematic designator U12)
U9 "TLV1702AIDGK" DGK0008A_N#2 1495,715 r0 top (schematic designator U10)
U10 "LP2992AILD-5.0/NOPB" LDE06A 1590,3985 r0 top (schematic designator U1)
U11 "REF2033AIDDCR" DDC0005A_N 1530,3425 r180 top (schematic designator U6)
U12 "REF2025DBV" DBV0005A_N 1520,3700 r180 top (schematic designator U3)
ZZ1 "These assemblies are ESD sensitive, ESD precautions shall be observed." AssemblyNote 100,6064 r0 top
ZZ2 "These assemblies must be clean and free from flux and all contaminants. Use of no clean flux is not acceptable." AssemblyNote 100,5979 r0 top (schematic designator ZZ3)
ZZ3 "These assemblies must comply with workmanship standards IPC-A-610 Class 2, unless otherwise specified." AssemblyNote 100,5904 r0 top

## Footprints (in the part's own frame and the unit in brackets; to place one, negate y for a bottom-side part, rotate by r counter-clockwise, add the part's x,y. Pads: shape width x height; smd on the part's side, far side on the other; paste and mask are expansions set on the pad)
0402 [mm] "0402 from SM-752 data"
  rect 0.8x0.6 smd: 1(-0.6,0) 2(0.6,0)
  silkscreen extent -1.22,-0.52 1.22,0.52, body extent -0.55,-0.3 0.55,0.3, height 0.6
0603 [mm] "0603 from SM-752 data"
  rect 1x0.95 smd: 1(-0.8,0) 2(0.8,0)
  silkscreen extent -1.52,-0.69 1.52,0.69, body extent -0.87,-0.47 0.87,0.47, height 0.85
0805_140 [mm] "0805 / 1.4mm height"
  rect 1.15x1.45 smd: 1(-0.9,0) 2(0.9,0)
  silkscreen extent -0.1,-0.8 0.1,0.8, body extent -1.1,-0.72 1.1,0.72, height 1.4
0805_HV [mil] "0805 with 30mil clearance between pads"
  rect 50x63 smd: 1(-40,0) 2(40,0)
  silkscreen extent -74,-40 74,40, body extent -43,-29 43,29, height 43
1206 [mm] "1206 from SM-752 data"
  rect 1.3x1.85 smd: 1(-1.45,0) 2(1.45,0)
  silkscreen extent -2.4,-1.21 2.4,1.21, body extent -1.7,-0.9 1.7,0.9, height 1.35
1210 [mm] "1210 from SM-752 data"
  rect 1.3x2.7 smd: 1(-1.45,0) 2(1.45,0)
  silkscreen extent -2.32,-1.57 2.32,1.57, body extent -1.7,-1.35 1.7,1.35, height 1.35
AssemblyNote [mil] "Assembly Note"
CONN_90120-0122 [mm] "Molex"
  rect 1.65x1.65 hole 1.016 mask+0.076: 1(-1.27,0)
  round 1.65 hole 1.016 mask+0.076: 2(1.27,0)
  silkscreen extent -3.56,-1.27 2.54,1.27, body extent -2.54,-1.27 2.54,1.27, height 9.29
D0008A_N [mm] "SOIC, 8-Leads, Body 4.9x3.9mm, Pitch 1.27mm, IPC Medium Density"
  oval 2.2x0.6 smd: 1(-2.4,1.905) 2(-2.4,0.635) 3(-2.4,-0.635) 4(-2.4,-1.905) 5(2.4,-1.905) 6(2.4,-0.635) 7(2.4,0.635) 8(2.4,1.905)
  silkscreen extent -0.9,-2.5 0.9,2.5, body extent -3,-2.45 3,2.45, height 1.63
DBV0005A_N [mm] "SOT23, 5-Leads, Body 2.9x1.6mm, Pitch 0.95mm, Lead Span 2.8mm, IPC Medium Density"
  rect 1.1x0.65 smd: 1(-1.2,0.95) 2(-1.2,0) 3(-1.2,-0.95) 4(1.2,-0.95) 5(1.2,0.95)
  silkscreen extent -0.25,-1.55 0.25,1.55, body extent -1.42,-1.46 1.42,1.46, height 1.08
DDC0005A_N [mil]
  rect 62x22 smd: 1(-46,37.4) 2(-46,0) 3(-46,-37.4) 4(46,-37.4) 5(46,37.4)
  silkscreen extent -35,-60 35,60, body extent -60,-60 60,60, height 43
DGK0008A_N#1 [mm] "TSOP, 8-Leads, Body 3x3mm, Pitch 0.65mm, IPC Medium Density"
  oval 1.7x0.45 smd mask+0.05: 1(-2.1,0.975) 2(-2.1,0.325) 3(-2.1,-0.325) 4(-2.1,-0.975) 5(2.1,-0.975) 6(2.1,-0.325) 7(2.1,0.325) 8(2.1,0.975)
  silkscreen extent -0.95,-1.55 0.95,1.55, body extent -2.45,-1.5 2.45,1.5, height 0.94
DGK0008A_N#2 [mm] "TSOP, 8-Leads, Body 3x3mm, Pitch 0.65mm, IPC Medium Density"
  oval 1.7x0.45 smd mask+0.051: 1(-2.1,0.975) 2(-2.1,0.325) 3(-2.1,-0.325) 4(-2.1,-0.975) 5(2.1,-0.975) 6(2.1,-0.325) 7(2.1,0.325) 8(2.1,0.975)
  silkscreen extent -2.75,-1.55 0.95,1.55, body extent -2.45,-1.5 2.45,1.5, height 0.94
DGN0008D_N [mm] "TSOP, 8-Leads, Body 3x3mm, Pitch 0.65mm, Thermal Pad 1.89x1.57mm, IPC Medium Density"
  oval 1.7x0.45 smd mask+0.051: 1(-2.1,0.975) 2(-2.1,0.325) 3(-2.1,-0.325) 4(-2.1,-0.975) 5(2.1,-0.975) 6(2.1,-0.325) 7(2.1,0.325) 8(2.1,0.975)
  rect 1.57x1.89 smd: 9(0,0)
  silkscreen extent -2.29,1.47 0.85,1.83, body extent -2.45,-1.5 2.45,1.5, height 0.94
Fiducial10-20 [mm]
  round 1 smd mask+0.5: 1(0,0)
  Top Layer keep-out circle w1.178: c0,0 r0.5
HSEC8-130-01-L-DV-A [mm]
  rect 0.5x1.2 smd: 121(11.6,1.7) 122(11.6,-1.7) 123(10.8,1.7) 124(10.8,-1.7) 125(10,1.7) 126(10,-1.7) 127(9.2,1.7) 128(9.2,-1.7) 129(8.4,1.7) 130(8.4,-1.7) 131(7.6,1.7) 132(7.6,-1.7) 133(6.8,1.7) 134(6.8,-1.7) 135(6,1.7) 136(6,-1.7) 137(5.2,1.7) 138(5.2,-1.7) 139(4.4,1.7) 140(4.4,-1.7) 141(3.6,1.7) 142(3.6,-1.7) 143(2.8,1.7) 144(2.8,-1.7) 145(2,1.7) 146(2,-1.7) 147(1.2,1.7) 148(1.2,-1.7) 149(0.4,1.7) 150(0.4,-1.7) 151(-0.4,1.7) 152(-0.4,-1.7) 153(-1.2,1.7) 154(-1.2,-1.7) 155(-2,1.7) 156(-2,-1.7) 157(-2.8,1.7) 158(-2.8,-1.7) 159(-3.6,1.7) 160(-3.6,-1.7) 161(-4.4,1.7) 162(-4.4,-1.7) 163(-5.2,1.7) 164(-5.2,-1.7) 165(-6,1.7) 166(-6,-1.7) 167(-6.8,1.7) 168(-6.8,-1.7) 169(-7.6,1.7) 170(-7.6,-1.7) 171(-8.4,1.7) 172(-8.4,-1.7) 173(-9.2,1.7) 174(-9.2,-1.7) 175(-10,1.7) 176(-10,-1.7) 177(-10.8,1.7) 178(-10.8,-1.7) 179(-11.6,1.7) 180(-11.6,-1.7)
  round 0 hole 1.27 unplated mask+0.889: 181(13.1,0) 182(-13.1,-1.5)
  silkscreen extent -14.3,-3.55 14.3,3.5
HSEC8-160-01-L-DV-A-L [mm] "CONN HIGH SPD CARD EDGE 120 POS"
  rect 0.5x1.2 smd: 1(25.2,1.7) 2(25.2,-1.7) 3(24.4,1.7) 4(24.4,-1.7) 5(23.6,1.7) 6(23.6,-1.7) 7(22.8,1.7) 8(22.8,-1.7) 9(22,1.7) 10(22,-1.7) 11(21.2,1.7) 12(21.2,-1.7) 13(20.4,1.7) 14(20.4,-1.7) 15(19.6,1.7) 16(19.6,-1.7) 17(18.8,1.7) 18(18.8,-1.7) 19(18,1.7) 20(18,-1.7) 21(17.2,1.7) 22(17.2,-1.7) 23(16.4,1.7) 24(16.4,-1.7) 25(15.6,1.7) 26(15.6,-1.7) 27(14.8,1.7) 28(14.8,-1.7) 29(14,1.7) 30(14,-1.7) 31(13.2,1.7) 32(13.2,-1.7) 33(12.4,1.7) 34(12.4,-1.7) 35(11.6,1.7) 36(11.6,-1.7) 37(10.8,1.7) 38(10.8,-1.7) 39(10,1.7) 40(10,-1.7) 41(9.2,1.7) 42(9.2,-1.7) 43(8.4,1.7) 44(8.4,-1.7) 45(7.6,1.7) 46(7.6,-1.7) 47(6.8,1.7) 48(6.8,-1.7) 49(6,1.7) 50(6,-1.7) 51(5.2,1.7) 52(5.2,-1.7) 53(4.4,1.7) 54(4.4,-1.7) 55(3.6,1.7) 56(3.6,-1.7) 57(-0.4,1.7) 58(-0.4,-1.7) 59(-1.2,1.7) 60(-1.2,-1.7) 61(-2,1.7) 62(-2,-1.7) 63(-2.8,1.7) 64(-2.8,-1.7) 65(-3.6,1.7) 66(-3.6,-1.7) 67(-4.4,1.7) 68(-4.4,-1.7) 69(-5.2,1.7) 70(-5.2,-1.7) 71(-6,1.7) 72(-6,-1.7) 73(-6.8,1.7) 74(-6.8,-1.7) 75(-7.6,1.7) 76(-7.6,-1.7) 77(-8.4,1.7) 78(-8.4,-1.7) 79(-9.2,1.7) 80(-9.2,-1.7) 81(-10,1.7) 82(-10,-1.7) 83(-10.8,1.7) 84(-10.8,-1.7) 85(-11.6,1.7) 86(-11.6,-1.7) 87(-12.4,1.7) 88(-12.4,-1.7) 89(-13.2,1.7) 90(-13.2,-1.7) 91(-14,1.7) 92(-14,-1.7) 93(-14.8,1.7) 94(-14.8,-1.7) 95(-15.6,1.7) 96(-15.6,-1.7) 97(-16.4,1.7) 98(-16.4,-1.7) 99(-17.2,1.7) 100(-17.2,-1.7) 101(-18,1.7) 102(-18,-1.7) 103(-18.8,1.7) 104(-18.8,-1.7) 105(-19.6,1.7) 106(-19.6,-1.7) 107(-20.4,1.7) 108(-20.4,-1.7) 109(-21.2,1.7) 110(-21.2,-1.7) 111(-22,1.7) 112(-22,-1.7) 113(-22.8,1.7) 114(-22.8,-1.7) 115(-23.6,1.7) 116(-23.6,-1.7) 117(-24.4,1.7) 118(-24.4,-1.7) 119(-25.2,1.7) 120(-25.2,-1.7)
  round 0 hole 1.27 unplated mask+0.889: 121(-26.7,-1.5) 122(26.7,0)
  silkscreen extent -35.4,-3.56 35.4,3.5
JOHNSON_142-0701-20X [mil] "Johnson Components recommended land pattern"
  round 95 hole 62: 1(0,0)
  round 100 hole 67: 2(100,100) 3(100,-100) 4(-100,-100) 5(-100,100)
  silkscreen extent -160,-160 160,160, body extent -156,-156 156,156, height 375
Keystone_1902C [mil] "Hex Standoff, 4-40 threaded, nylon"
  round 1 on Mech4: 0(0,0)
  body extent -145,-126 146,126, height 501
LAH25-NP [mm] "TH, 9-Leads, Body 14.93x33.3mm"
  rect 2x2 hole 1.5: 1(-5.715,11.43)
  round 2 hole 1.5: 2(-5.715,8.89) 3(-5.715,6.35) 4(5.715,6.35) 5(5.715,8.89) 6(5.715,11.43)
  round 1.7 hole 1.2: 7(3.81,-6.35) 8(3.81,-8.89) 9(3.81,-11.43)
  silkscreen extent -7.9,-14.12 7.47,19.18, body extent -7.44,-14.12 7.5,19.18, height 21.15
LDE06A [mm] "PSON, 6-Leads, Body 2.92x3.29 mm, Pitch 0.95mm, NSC Recommended"
  rect 0.5x0.35 smd paste-0.175 mask+0.064: 1(-1.295,0.95) 2(-1.295,0) 3(-1.295,-0.95) 4(1.295,-0.95) 5(1.295,0) 6(1.295,0.95)
  rect 1.2x1.92 smd paste-0.6 mask+0.051: 7(0,0)
  silkscreen extent -2.52,-1.66 1.85,1.67, body extent -1.69,-1.51 1.69,1.51, height 0.8
LED0603AA [mil]
  rect 32x32 smd: 1(-32.48,0) 2(32.48,0)
  silkscreen extent -129,-24 11,27
Molex_39357-0002 [mm] "Terminal Block, 3.5 mm, 2x1, TH"
  rect 1.6x1.6 hole 1.1: 1(-1.75,0)
  round 1.6 hole 1.1: 2(1.75,0)
  silkscreen extent -3.86,-3.45 3.5,3.84, body extent -3.55,-3.45 3.56,3.84, height 8.51
Molex_39357-0003 [mm] "Terminal Block, 3.5 mm, 3x1, TH"
  rect 1.6x1.6 hole 1.1: 1(-3.5,0)
  round 1.6 hole 1.1: 2(0,0) 3(3.5,0)
  silkscreen extent -5.61,-3.45 5.25,3.84, body extent -5.25,-3.45 5.16,3.84, height 8.51
"NY PMS 440 0025 PH" [mm] "4-40 nylon screw and mounting hole"
  round 8 hole 3.2: 1(0,0)
  body extent -3.3,-3.3 3.3,3.3, height 2.69
Pb-Free_Overlay_Small [mil]
  silkscreen extent -46,-46 46,46
PhoenixContact_1715721 [mm] "Phoenix Contact 1715721 used on LM3445 design from Longmont"
  rect 1.905x1.905 hole 1.3: 1(-2.54,0)
  round 1.9 hole 1.3: 2(2.54,0)
  silkscreen extent -5.97,-4.75 5.28,5.36, body extent -5.82,-4.6 5.08,5.2, height 14.2
RGT0016C [mm] "QFN, 16-Leads, Body 3x3mm, Pitch 0.5mm, Thermal Pad 1.7x1.7mm, TI Recommended"
  oval 0.6x0.24 smd: 1(-1.4,0.75) 2(-1.4,0.25) 3(-1.4,-0.25) 4(-1.4,-0.75) 9(1.4,-0.75) 10(1.4,-0.25) 11(1.4,0.25) 12(1.4,0.75)
  oval 0.24x0.6 smd: 5(-0.75,-1.4) 6(-0.25,-1.4) 7(0.25,-1.4) 8(0.75,-1.4) 13(0.75,1.4) 14(0.25,1.4) 15(-0.25,1.4) 16(-0.75,1.4)
  rect 1.7x1.7 smd paste-0.85 mask+0.064: 17(0,0)
  silkscreen extent -1.72,-1.73 1.72,1.73, body extent -1.57,-1.57 1.58,1.58, height 1.01
SMA [mm] "Molded Diode, 2-Leads, Body 4.3x2.6mm, IPC Medium Density, based on OnSemi component dimensions and land pattern"
  rect 2x2 smd: 1(-2,0) 2(2,0)
  silkscreen extent -3.66,-1.57 2.79,1.57, body extent -2.6,-1.3 2.6,1.3, height 2.42
SOD-123#1 [mm] "On Semi recommended land pattern"
  rect 0.915x1.22 smd: 1(-1.637,0) 2(1.637,0)
  silkscreen extent -2.74,-1.17 2.03,1.17, body extent -1.93,-0.9 1.93,0.9, height 1.35
SOD-123#2 [mm] "On Semi recommended land pattern"
  rect 0.915x1.22 smd mask+0.064: 1(-1.637,0) 2(1.637,0)
  silkscreen extent -2.74,-1.17 2.03,1.17, body extent -1.93,-0.9 1.93,0.9, height 1.35
TI_STACKED_OVERLAY_MEDIUM [mil]
  silkscreen extent -576,-136 576,134
WURTH_61300611121 [mm] "Header, 2.54mm, 6x1, TH"
  rect 1.65x1.65 hole 1.15: 1(-6.35,0)
  round 1.65 hole 1.15: 2(-3.81,0) 3(-1.27,0) 4(1.27,0) 5(3.81,0) 6(6.35,0)
  silkscreen extent -7.62,-1.27 7.62,1.6, body extent -7.62,-1.27 7.62,1.27, height 8.54
XFL4020 [mm] "Coilcraft XFL4020 7/18/12"
  rect 0.98x3.4 smd: 1(-1.181,0) 2(1.181,0)
  silkscreen extent -2.16,-2.16 2.16,2.16, body extent -2.15,-2.15 2.15,2.15, height 2.1

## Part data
C1: "CAP, CERM, 10 µF, 35 V, +/- 20%, X7R, 1206_190"
C2: "CAP, CERM, 3300 pF, 50 V, +/- 10%, X7R, 0805"
C3 C4 C5 C10 C11 C23: "CAP, CERM, 100 pF, 100 V, +/- 5%, C0G/NP0, 0603"
C6 C8 C20 C21 C29 C36 C38 C54 C56: "CAP, CERM, 10 µF, 25 V, +/- 10%, X5R, 0805_140"
C7 C13 C18 C22 C30 C31 C32 C33 C34 C35 C37 C53 C55: "CAP, CERM, 0.1 µF, 50 V, +/- 10%, X7R, 0603"
C9 C12: "CAP, CERM, 22 µF, 16 V, +/- 10%, X5R, 0805"
C14: "CAP, CERM, 2700 pF, 50 V, +/- 5%, C0G/NP0, 0603"
C15 C16 C58 C59: "CAP, CERM, 0.01 µF, 25 V, +/- 5%, C0G/NP0, 0603"
C17 C24 C25 C47 C48 C49 C50 C51 C52: "CAP, CERM, 1uF, 10V, +/-10%, X7R, 0805"
C19: "CAP, CERM, 470 pF, 50 V, +/- 5%, C0G/NP0, 0603"
C26 C57: "CAP, CERM, 200 pF, 100 V, +/- 5%, C0G/NP0, 0603"
C27 C28: "CAP, CERM, 820 pF, 50 V, +/- 5%, C0G/NP0, 0603"
C39 C40 C41 C44 C45 C46 C61: "CAP, CERM, 330 pF, 50 V, +/- 1%, C0G/NP0, 0603"
C42 C43: "CAP, CERM, 4.7 µF, 10 V, +/- 10%, X5R, 0603"
C60: "CAP, CERM, 0.01 µF, 50 V, +/- 5%, X7R, 0402"
D1 D2 D5 D6 D7 D8 D9: "Diode, Schottky, 40 V, 0.015 A, SOD-123"
D3 D4: "Diode, Schottky, 60V, 1A, SMA"
D10 D11 D12 D13: "Diode, Zener, 3.6V, 500mW, SOD-123"
FID1 FID2 FID3 FID4 FID5 FID6: "Fiducial mark.  There is nothing to buy or mount."
H1 H2 H3 H4: "Machine Screw, Round, #4-40 x 1/4, Nylon, Philips panhead"
H9 H10 H11 H12: "Standoff, Hex, 0.5\"L #4-40 Nylon"
J1: "Conn Term Block, 2POS, 5.08mm, TH"
J2: "Terminal Block, 3.5 mm, 2x1, Tin, TH"
J3: "Terminal Block, 3.5 mm, 3x1, Tin, TH"
J4 J12: "Header, 2.54 mm, 6x1, Gold, TH"
J5 J6 J7 J8: "Connector, TH, SMA"
J9: "Header, 100mil, 2x1, Tin, TH"
J10: library part HSEC8-130-01-L-DV-A, "CONN HIGH SPD CARD EDGE 60 POS"
J11: library part HSEC8-160-01-L-DV-A-L, "CONN HIGH SPD CARD EDGE 120 POS"
L1: "Inductor, Shielded, Composite, 2.2 µH, 3.7 A, 0.02 ohm, SMD"
LD1 LD2: "LED SmartLED Green 570NM"
Logo1: library part TI_Logo, "Texas Instrument Corporate Signature"
Logo2: library part Pb-Free
R1 R2: "RES, 0, 5%, 0.1 W, 0603"
R3 R4 R7 R9 R24 R25 R36 R38 R39 R41 R46 R47 R50 R51 R54 R60 R62 R63 R64 R65 R66 R67 R68 R69 R70 R71 R72 R73 R74 R75 R76 R77 R78 R79 R80 R81 R82 R83 R84 R92 R95 R96 R97 R98: "RES, 0 ohm, 5%, 0.1W, 0603"
R5: "RES, 154 k, 1%, 0.1 W, 0603"
R6: "RES, 42.2, 1%, 0.125 W, 0805"
R8: "RES, 1.00 k, 1%, 0.1 W, 0603"
R10 R11 R12 R14 R15 R16 R17 R18 R19 R20 R21 R23 R27 R28 R29 R91: "RES, 2.00 k, 1%, 0.1 W, 0603"
R13: "RES, 1.0 M, 5%, 0.1 W, 0603"
R22 R34: "RES, 673, 0.1%, 0.1 W, 0603"
R26: "RES, 5.23 k, 1%, 0.1 W, 0603"
R30 R32: "RES, 18.2 k, 1%, 0.1 W, 0603"
R31 R33 R37 R40: "RES, 2.00 k, 0.1%, 0.1 W, 0603"
R35: "RES, 1.15 k, 1%, 0.1 W, 0603"
R42: "RES, 9.76 k, 1%, 0.1 W, 0603"
R43 R45: "RES, 43.2 k, 1%, 0.1 W, 0603"
R44: "RES, 20.0 k, 1%, 0.1 W, 0603"
R48 R49: "RES, 24.9, 1%, 0.1 W, 0603"
R52: "RES, 10.0 k, 1%, 0.1 W, 0603"
R53 R55 R93 R94: "RES, 511, 0.5%, 0.1 W, 0603"
R56: "RES, 2.49 k, 1%, 0.1 W, 0603"
R57 R58 R59 R61: "RES, 22, 5%, 0.1 W, 0603"
R85 R86 R87 R88 R89 R90: "RES, 0, 5%, 0.25 W, 1206"
U1: "Buck Step Down Regulator with 3 to 17 V Input and 0.9 to 6 V Output, -40 to 85 degC, 16-Pin QFN (RGT), Green (RoHS & no Sb/Br)"
U2: "Current Transducer, 25A, TH"
U3: "20 MHz, Low Noise, RRIO, CMOS Operational Amplifier with Shutdown, 1.8 to 5.5 V, -40 to 125 degC, 5-pin SOT23 (DBV0005A), Green (RoHS & no Sb/Br)"
U4: "Single Output High PSRR LDO, 200 mA, Adjustable -1.18 to -33 V Output, -3 to -36 V Input, with Ultra-Low Noise, 8-pin MSOP (DGN), -40 to 125 degC, Green (RoHS & no Sb/Br)"
U5: "Single Output High PSRR LDO, 150 mA, Adjustable 1.2 to 33 V Output, 3 to 36 V Input, with Ultra-Low Noise, 8-pin MSOP (DGN), -40 to 125 degC, Green (RoHS & no Sb/Br)"
U6: "High Voltage, Rail-to-Rail Input/Output, Precision Operational Amplifiers, e-trim™ Series, D0008A"
U7: "20 MHz, Low Noise, RRIO, CMOS Operational Amplifier, 1.8 to 5.5 V, -40 to 125 degC, 8-pin SOIC (D0008A), Green (RoHS & no Sb/Br)"
U8: "Ultra Low Power, Rail-to-Rail Output, Fully-Differential Amplifier, DGK0008A"
U9: "2.2-V to 36-V, microPower Comparator, DGK0008A"
U10: "Micropower 250 mA Low-Noise Ultra Low-Dropout Regulator, 6-pin LLP, Pb-Free"
U11: "Low-Drift, Low-Power, Dual-Output, VREF and VREF / 2 Voltage References, DDC0005A"
U12: "DUAL OUTPUT VOLTAGE REFERENCE 2.5V, DBV0005A"
ZZ1 ZZ2 ZZ3: library part AssemblyNote

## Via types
v1: diameter 32, hole 16, Top Layer to Bottom Layer, 160 vias
v2: diameter 24, hole 12, Top Layer to Bottom Layer, 40 vias
v3: diameter 19.68, hole 7.87, Top Layer to Bottom Layer, 16 vias
v4: diameter 30, hole 16, Top Layer to Bottom Layer, 5 vias

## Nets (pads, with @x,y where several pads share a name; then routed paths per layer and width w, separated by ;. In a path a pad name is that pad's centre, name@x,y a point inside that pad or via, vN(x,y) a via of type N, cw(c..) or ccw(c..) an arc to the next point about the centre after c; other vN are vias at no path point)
AINM_D: C27.1 C40.2 D11.1 J6.1 J12.4 R37.2 R48.1 R59.1 | length 3148.5
  Top Layer w10: R37.2@1316.48,2717.2 1316.48,2758.48 1346.7,2788.7 C27.1@1394.98,2788.7 1553.3,2788.7 1596.48,2745.52 R48.1@1596.48,2587.2 1620.68,2563 1822,2563 1849,2590 1849,2786 J6.1@1845,2790 ; v2(2105,2615) 2105,2625 2178,2698 2178,3252 2225,3299 2246.24,3299 C40.2@2267.73,3277.5 2267.73,3207.5 R59.1@2271.24,3204 2271.24,3178.76 2293,3157 v2(2301,3157)
  Bottom Layer w10: J6.1@1845,2790 1965,2790 2024.47,2730.53 D11.1@2080,2730.53 2080,2640 v2(2105,2615) ; v2(2301,3157) 2301,3346 2454,3499 2745,3499 2793,3451 J12.4@2882,3451
AINP_1: C39.1 C57.1 D10.1 J5.1 J12.1 R41.1 R57.1 U7.7 | length 2604.2
  Top Layer w10: U7.7@1134.92,3085 1208,3085 v2(1209,3084) ; R41.1@1341.93,3090 1346.93,3085 v2(1395,3085) 1453.5,3085 1455,3083.5 1548.5,3083.5 1610,3145 J5.1@1845,3145 2077.53,3145 D10.1@2078,3145.47 2078,3725 2173.5,3820.5 v2(2206,3820.5) 2267.2,3820.5 C39.1@2267.2,3755.5
  Bottom Layer w10: v2(1209,3084) 1211.5,3086.5 C57.1@1340,3086.5 ; C57.1@1340.43,3086.5 1393.5,3086.5 v2(1395,3085) ; v2(2206,3820.5) 2496.5,3820.5 2566,3751 J12.1@2882,3751
AINP_2: C19.1 C41.1 D13.1 J8.1 J12.2 R34.2 R61.1 U6.7 | length 4570.1
  Top Layer w10: U6.7@1120.06,1279.22 v2(1195.57,1279.22) 1235.57,1319.22 R34.2@1269.07,1319.22 ; C19.1@1332.06,1179.22 1380.57,1179.22 v2(1389.85,1188.5) J8.1@1843.5,1188.5 ; v2(2187,3619) 2272.5,3619 R61.1@2273.5,3620 2273.5,3555 C41.1@2270,3551.5
  Bottom Layer w10: v2(1195.57,1279.22) 1286.28,1188.5 v2(1389.85,1188.5) ; J8.1@1845,1190 2074.47,1190 D13.1@2080,1184.47 2079,1185.47 2079,1301 2274.5,1496.5 2274.5,3220.96 2186,3309.46 2186,3620 v2(2187,3619) 2219,3651 J12.2@2882,3651
AINP_D: C28.1 C40.1 D12.1 J7.1 J12.3 R40.2 R49.1 R58.1 | length 3131.7
  Top Layer w10: R40.2@1326.48,2357.2 1362.97,2320.7 C28.1@1404.98,2320.7 1404.98,2282.02 1435,2252 1551,2252 1596.48,2297.48 R49.1@1596.48,2517.2 1597.76,2517.2 1625.56,2545 1825,2545 1851,2519 1851,2366 J7.1@1845,2360 1967,2360 2030.47,2423.47 D12.1@2080,2423.47 2080,2630 2160,2710 2160,3259.46 2220.54,3320 2247,3320 2267.5,3340.5 C40.1@2267.73,3340.5 2271.24,3344 R58.1@2271.24,3414 2220,3414 v2(2219,3415)
  Bottom Layer w10: v2(2219,3415) 2344.54,3415 2446.54,3517 2744,3517 2778,3551 J12.3@2882,3551
GND: C1.2 C2.2 C3.2 C4.2 C6.2 C7.2 C8.2 C9.2 C12.2 C13.2 C14.2 C17.2 C18.2 C20.2 C21.2 C22.2 C23.2 C24.2 C25.2 C29.2 C30.2 C31.2 C32.2 C33.2 C34.2 C35.2 C36.2 C37.2 C38.2 C39.2 C41.2 C42.2 C43.2 C44.2 C45.2 C47.2 C48.2 C49.2 C50.2 C51.2 C52.2 C53.2 C54.2 C55.2 C56.2 C58.2 C59.2 C60.2 C61.2 D1.2 D5.2 D8.2 D9.2 D10.2 D11.2 D12.2 D13.2 J2.2 J3.2 J4.5 J4.6 J5.2 J5.3 J5.4 J5.5 J6.2 J6.3 J6.4 J6.5 J7.2 J7.3 J7.4 J7.5 J8.2 J8.3 J8.4 J8.5 J9.2 J12.5 J12.6 LD1.1 LD2.1 R2.1 R4.2 R5.1 R6.1 R12.2 R17.1 R23.1 R28.1 R29.1 R53.2 R65.1 R66.1 R69.1 R70.1 R71.1 R73.1 R77.2 R78.1 R79.1 R80.1 R81.1 R82.1 R83.1 R95.1 R96.1 R97.1 U1.6 U1.8 U1.15 U1.16 U1.17 U3.2 U4.4 U4.9 U5.4 U5.9 U7.4 U8.6 U10.2 U10.7 U11.2 U12.2 | length 5433.7
  Top Layer w8: U1.17@551.47,3732.53 U1.8@551.47,3758.12 ; v3(557.38,3726.62) U1.17@581,3703 ; 590.84,3625.16 U1.15@590.84,3647.88 U1.17@590.84,3693.16 ; U1.6@590.84,3758.12 590.84,3712.84 U1.17@581,3703 ; 610.53,3621.47 U1.16@610.53,3647.88 610.53,3657.47 604.62,3663.38 v3(604.62,3679.38) U1.17@590.84,3693.16 ; U1.17@581,3703 U1.17@590.84,3693.16
  Top Layer w12: 569,3573 590.84,3594.84 590.84,3625.16 ; 610.53,3574.53 610.53,3621.47 ; v1(1474,3964) 1487,3964 1508,3985 U10.2@1539.02,3985
  Top Layer w15: v1(438,1351) 439,1350 D1.2@481.53,1350 ; U4.4@952.68,688.39 988.39,688.39 v1(1006.07,706.07) ; U5.4@964.96,969.76 U5.4@964.96,969.76 v1(965,1005) ; U8.6@1432.78,2634.88 1432.78,2682.78 v1(1450,2700) ; v2(2215,3895) C42.2@2273.5,3895 ; v1(2222,3045) v1@2224,3047 ; v2(2827,133) C47.2@2827,198
  Top Layer w20: v1(397,2296) R6.1@397,2363 ; v4(397.5,1134.5) R4.2@397.5,1195 ; v1(489,1125) R12.2@542.5,1125 ; v1(540,2385) 540.53,2385.53 D5.2@540.53,2455 ; C3.2@570,3116.5 v1(570,3170) ; C4.2@588.5,2710 v1(588.5,2761.5) ; v1(648,493) 650,493 670,513 C6.2@670,546.57 ; v1(685,780) C8.2@685,834.57 ; v1(740,2900) 740.53,2900.53 D8.2@805,2900.53 ; v1(750,2510) 759,2501 U3.2@802.4,2501 ; C7.2@764.5,1178 764.5,1129.5 v1(766,1128) ; R17.1@826.93,3275 v1(875,3275) ; v1(880,2965) 900,2985 U7.4@945.94,2985 ; LD1.1@980,3773.48 v1(1024.52,3773.48) ; v1(986,1110) R53.2@1042.5,1110 ; v1(1006.07,706.07) 1015,715 R28.1@1053.5,715 ; v1(1039,1060) 1039.79,1059.21 R29.1@1039.79,1017.38 ; R23.1@1056.48,2457.2 C13.2@1056.5,2545 v1(1105,2545) ; v1(1165,2190) C17.2@1164.98,2252.2 ; C14.2@1172.06,1414.22 1218.84,1461 v1(1233,1461) ; C20.2@1190,645.43 v1(1190,687) ; v1(1205,770) C21.2@1205,819.57 ; v1(1225,3740) C24.2@1285,3740 ; v1(1230,3465) C25.2@1285,3465 ; v1(1327,4042) C29.2@1382.57,4042 ; C18.2@1332.06,1384.22 1374.22,1384.22 v4(1382,1392) ; v1(1340,2905) 1341.93,2906.93 C23.2@1341.93,2955 ; C22.2@1341.5,3175 v1(1390,3175) ; C31.2@1474.98,2320.7 1501.7,2320.7 1507,2326 1539.62,2326 C60.2@1541,2327.38 v4(1541,2283) ; C30.2@1531.5,3585 1531.5,3553.5 v1(1555,3530) ; v1(1535,3860) C36.2@1584.57,3860 ; C32.2@1546.5,3300 v1(1595,3300) ; C33.2@1561.5,575 1600,575 v1(1615,560) ; U12.2@1567.24,3700 1600,3700 v1(1620,3720) ; U11.2@1576,3425 1632,3425 v1(1637,3430) ; C34.2@1631.5,915 v1(1685,915) ; C35.2@1643.5,3595 1643.5,3546.5 v1(1645,3547.99) ; v1(1647,4111) 1657.57,4100.43 C38.2@1712,4100.43 ; C37.2@1683.5,3470 v1(1683.5,3518.5) ; v1(1695,4155) 1696,4156 LD2.1@1737.52,4156 ; D9.2@2014.47,625 v1(2060,625) ; v1(2078,2965) D10.2@2078,3016.53 ; v1(2080,2235) D12.2@2080,2294.53 ; v1(2213,3693) 2213.5,3692.5 C39.2@2267.2,3692.5 C45.2@2337.2,3692.5 ; v1(2216,3487) 2268.5,3487 C41.2@2270,3488.5 C44.2@2335,3488.5 ; v4(2222,3111) C61.2@2273.5,3111 ; v1@2224,3047 C43.2@2275.5,3047 C43.2@2273.5,3049 ; v1(2237,896) R96.1@2294.5,896 ; v1(2240,550) R65.1@2293.5,550 ; v1(2245,205) R66.1@2298.5,205 ; C48.2@2830,555 v1(2830,620)
  Bottom Layer w15: v1(2439,3110) 2441,3112 2441.49,3111.51 R79.1@2488.07,3111.51 ; R81.1@2488.07,3457.97 2553.03,3457.97 v1(2567,3444) 2567.5,3444.5 R70.1@2623,3444.5
  Bottom Layer w20: v1(588.5,2761.5) v1@590,2760 ; v1(785,550) C59.2@785,598.5 ; C58.2@799.61,887.09 799.61,835.39 v1(800,835) ; v1(1435,1735) 1434.57,1735.43 C56.2@1434.57,1790 1438.5,1793.94 C55.2@1438.5,1865 ; C53.2@1676.5,1865 1676.5,1793.94 C54.2@1680.43,1790 v1(1730,1790) ; v1(2002,1011) 2046.53,1055.53 D13.2@2080,1055.53 ; D11.2@2080,2859.47 v1(2080,2910) ; v1(2434,3972) 2434.5,3971.5 R77.2@2490,3971.5 ; v1(2435,2355) 2435.61,2355.61 R82.1@2488.07,2355.61 ; v1(2435,2450) 2435.1,2450.1 R80.1@2488.07,2450.1 ; v1(2435.27,2135) 2435.14,2135.14 R83.1@2488.07,2135.14 ; R95.1@2488.07,2733.56 2542.56,2733.56 v1(2543,2734) ; R97.1@2488.07,3552.46 2542.46,3552.46 v1(2543,3553) ; R78.1@2490,3316.5 2538.5,3316.5 v1(2540,3315) ; R71.1@2621.93,3552.46 2682.46,3552.46 v1(2679.92,3555) ; R73.1@2621.93,3867.42 2677.42,3867.42 v1(2680,3870) ; R69.1@2625,3311.5 2678.5,3311.5 v1(2680,3310) ; C52.2@2705,2085 v1(2770,2085) ; C51.2@2710,2280 v1(2775,2280) ; C50.2@2710,2535 v1(2775,2535) ; C49.2@2710,3190 2710,3235 v1(2725,3250)
  other v1: 535,3400 472,3403 533,3461 471,3463 471,3517 534,3518 370,3909 448,3915 203,3937
  other v3: 852.28,626.38 887.72,626.38 870,650 852.28,673.62 887.72,673.62 864.57,907.76 900,907.76 882.28,931.38 864.57,955 900,955 557.38,3679.38 604.62,3726.62 1590,3960 1590,4010
IP_IN_1: J1.2 R88.1 U2.1 | length 635
  Bottom Layer w15: R88.1@740,1715 R88.1@742,1717
  Bottom Layer w50: J1.2@245,1715 726.91,1715 R88.1@727.91,1714 727.91,1667.09 U2.1@800,1595
IP_OUT_1: J1.1 R86.1 U2.4 | length 1118.2
  Top Layer w50: J1.1@245,1915 1116,1915 v1(1138,1937)
  Bottom Layer w50: U2.4@1000,2045 1048.09,1996.91 R86.1@1048.09,1940 1135,1940 v1(1138,1937)
ISENSE: J2.1 R3.2 R6.2 R7.2 R9.2 R84.2 R98.1 | length 6509.9
  Top Layer w20: J2.1@187,2441.9 R6.2@381.08,2441.9 ; R3.2@397.5,1270 v1(339,1270) 150,1459 150,2047.99 290,2187.99 290,2350.82 R6.2@381.08,2441.9 ; R7.2@420,3053.5 420,2829 348,2757 348,2492 R6.2@397,2443 ; R9.2@448.5,2640 448.5,2494.5 R6.2@397,2443 ; v1(1790,600) 1791.5,601.5 R98.1@1791.5,645 ; v1(1920,1970) 1750,2140 712,2140 410.1,2441.9 398.1,2441.9 R6.2@397,2443 ; R6.2@381.08,2441.9 395.9,2441.9 R6.2@397,2443
  Bottom Layer w20: v1(339,1270) 339,682 572,449 1639,449 v1(1790,600) ; R84.2@1866.5,1970 v1(1920,1970)
N12V: C7.1 C15.1 C20.1 C33.1 C55.1 C56.1 R30.2 R45.1 U2.7 U4.1 U6.4 U9.4 | length 488.4
  Top Layer w15: U4.1@952.68,611.61 982.12,611.61 1015.23,578.5 C15.1@1045,578.5 ; v1@1278,500 v1(1280,500) ; U9.4@1412.32,676.61 1449.96,676.61 1471.57,655
  Top Layer w20: v1(831,1123) 831,1174.5 C7.1@827.5,1178 828.72,1179.22 U6.4@931.08,1179.22 ; v1(1440,575) C33.1@1498.5,575 1498.5,628.07 1471.57,655
  Bottom Layer w15: v1@1523,1700 v1(1525,1700)
  other v1: 1098,500 1188,500 1493,1730
N15V: D4.1 J3.3
NetC1_1: C1.1 C8.1 D3.1 U1.10 U1.11 U1.12 U1.13 U5.5 U5.8 | length 3225.3
  Top Layer w8: 501.16,3712.84 U1.10@525.88,3712.84
  Top Layer w10: 515,3657 524.12,3647.88 U1.13@551.47,3647.88
  Top Layer w12: v1@286,3702 v1(287,3701) ; 469,3703 478.84,3712.84 501.16,3712.84
  Top Layer w15: 683,995 732,995 755.33,971.67 755.56,971.67 757.47,969.76 U5.5@799.61,969.76
  Top Layer w25: D3.1@569.92,965 v1(569.92,1049.92)
  Bottom Layer w30: v1(287,3659) 262,3659 82,3479 82,1618 569.92,1130.08 v1(569.92,1049.92)
NetC2_1: C2.1 U1.9 | length 163.8
  Top Layer w8: 492,3743 502.47,3732.53 U1.9@525.88,3732.53
  Top Layer w12: C2.1@373,3759 476,3759 492,3743
NetC3_1: C3.1 D7.2 D8.1 R14.2 R27.2 R91.2 U7.3 | length 740.7
  Top Layer w10: D8.1@805,3029.47 D8.1@810.53,3035
  Top Layer w15: R14.2@495,3053.5 C3.1@570,3053.5 606.5,3053.5 614.47,3045.53 D7.2@665,3045.53 734.47,3045.53 750.53,3029.47 D8.1@805,3029.47
  Top Layer w20: D8.1@810.53,3035 U7.3@945.94,3035 1000,3035 1043.5,2991.5 R27.2@1043.5,2900 1043.5,2831 R91.2@1044.5,2830
NetC4_1: C4.1 D5.1 D6.2 R15.2 R20.2 R21.2 U3.3 | length 415.5
  Top Layer w15: C4.1@651.5,2710 R15.2@651.5,2640 651.5,2592.97 D6.2@689.47,2555 689.47,2519.47 669.47,2499.47 D5.1@669.47,2455
  Top Layer w20: D5.1@669.47,2455 755,2455 763.6,2463.6 U3.3@802.4,2463.6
